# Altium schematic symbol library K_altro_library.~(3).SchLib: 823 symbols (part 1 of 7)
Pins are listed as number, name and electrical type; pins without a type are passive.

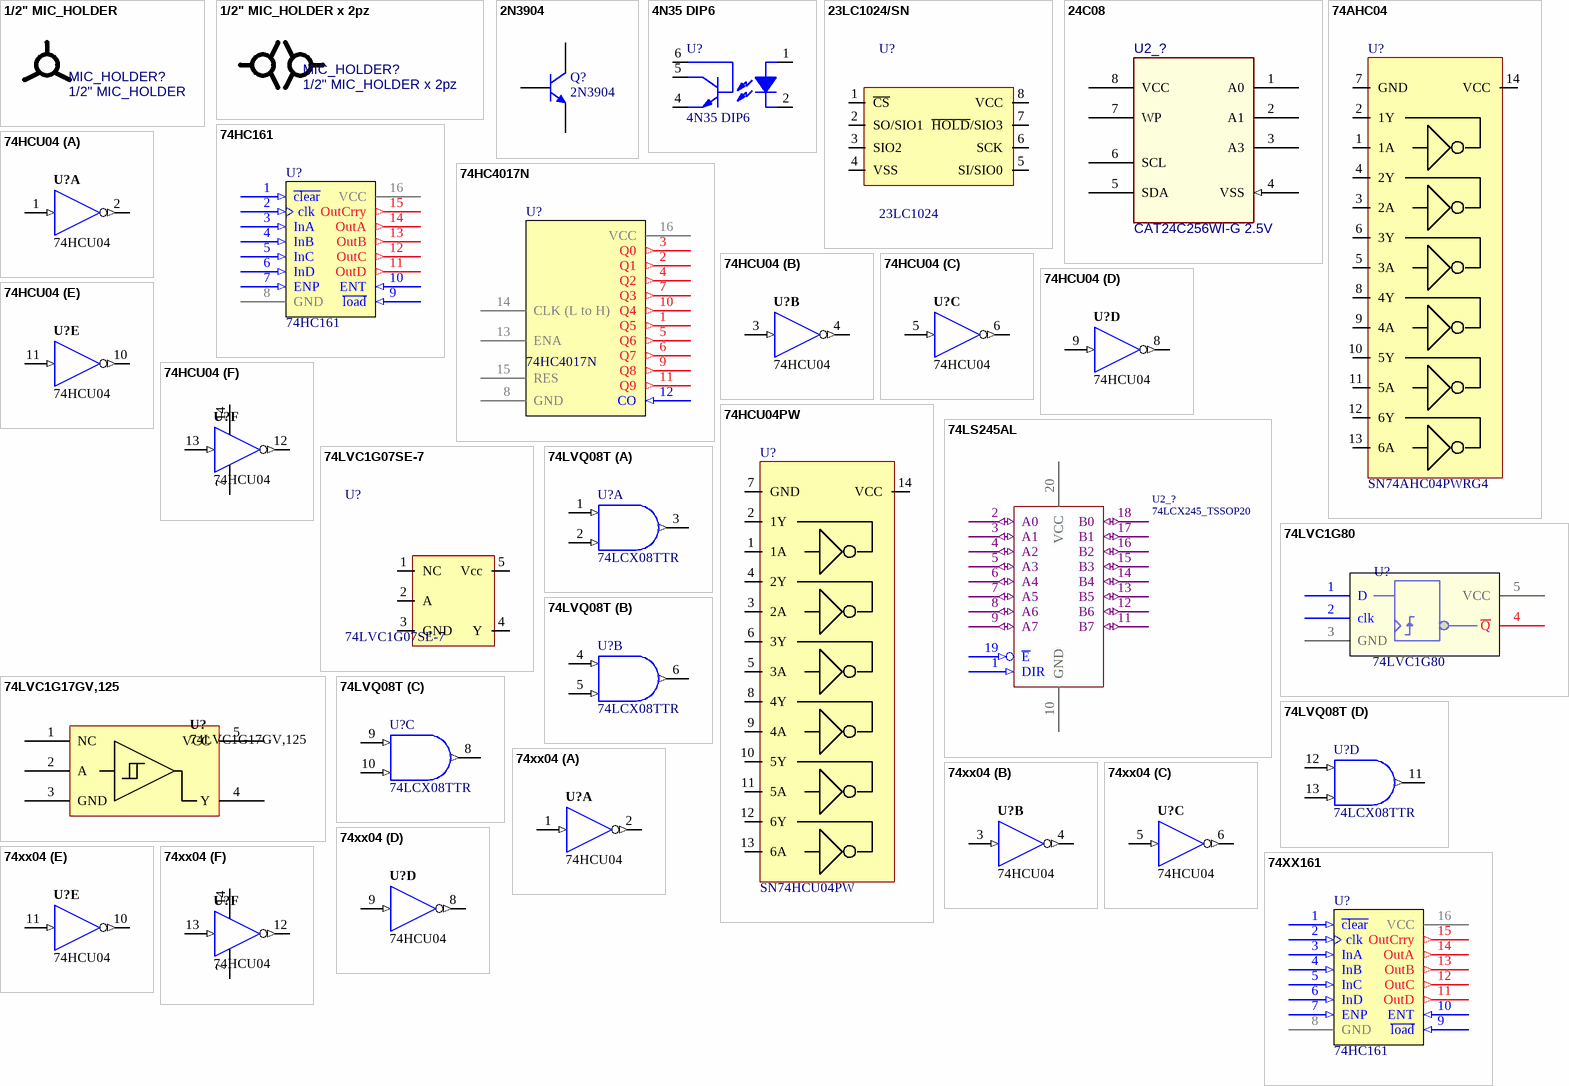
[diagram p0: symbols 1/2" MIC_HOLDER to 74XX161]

## 1/2" MIC_HOLDER
designator MIC_HOLDER?
Costo: 0,025; Aggiornato: S; ContoLavoro: 1
footprint MICROPHONE TSB-160AUC680-GP

## 1/2" MIC_HOLDER x 2pz
designator MIC_HOLDER?  (no BOM)
Costo: 0; Aggiornato: S; ContoLavoro: 1
footprint MICROPHONE_TSB-160AUC680-GP_Doppio_supporto

## 2N3904
designator Q?
NPN General Purpose Amplifier; Aggiornato: NO; Costo: 0
footprint TO-92A (TO, Flat Index; 3 In-Line, Axial Leads; Body Dia. 4.5mm; Leads 0.51 x 0.48 mm (max))
simulation model 2N3904 (NPN)
signal-integrity model 2N3904
pins: 1 E, 2 B, 3 C

## 4N35 DIP6
designator U?
Costo: 0; Aggiornato: NO
footprint DIP6
pins: 1, 2, 4, 5, 6

## 23LC1024/SN
designator U?, comment 23LC1024
23LC1024 1 Mbit SPI Bus Serial RAM 8 pin SOIC; MPN: 25AA1024; Costo: 0,39; Detail: € RS pz>40; Aggiornato: S; ContoLavoro: 0
footprint SOIC8
pins: 1 ~{CS}, 2 SO/SIO1, 3 SIO2, 4 VSS, 5 SI/SIO0, 6 SCK, 7 ~{HOLD}/SIO3, 8 VCC

## 24C08
designator U2_?, comment CAT24C256WI-G 2.5V
Aggiornato: NO; Costo: 0
footprint SO8
pins: 1 A0, 2 A1, 3 A3, 4 VSS (in), 5 SDA, 6 SCL, 7 WP, 8 VCC

## 74AHC04
designator U?, comment SN74AHC04PWRG4
Costo: 0,073; Aggiornato: NO; ContoLavoro: 0
footprint TSSOP14
pins: 1 1A, 2 1Y, 3 2A, 4 2Y, 5 3A, 6 3Y, 7 GND, 8 4Y, 9 4A, 10 5Y, 11 5A, 12 6Y, 13 6A, 14 VCC

## 74HC161
designator U?
74HC161 4 Bit Sync counter; Costo: 0,10; Aggiornato: s; ContoLavoro: 0
footprint tssop16
pins: 1 ~{clear} (in), 2 clk (in), 3 InA (in), 4 InB (in), 5 InC (in), 6 InD (in), 7 ENP (in), 8 GND (power), 9 ~{load} (in), 10 ENT (in), 11 OutD (out), 12 OutC (out), 13 OutB (out), 14 OutA (out), 15 OutCrry (out), 16 VCC (power)

## 74HC4017N
designator U?
Costo: 0,958; Aggiornato: s; ContoLavoro: 0
footprint DIP.100/16/W.300/L.775
pins: 1 Q5 (out), 2 Q1 (out), 3 Q0 (out), 4 Q2 (out), 5 Q6 (out), 6 Q7 (out), 7 Q3 (out), 8 GND (power), 9 Q8 (out), 10 Q4 (out), 11 Q9 (out), 12 CO (in), 13 ENA (power), 14 CLK (L to H) (power), 15 RES (power), 16 VCC (power)

## 74HCU04
designator U?
74HCU04, HEX Inverter, Unbuffered; Aggiornato: NO; Costo: 0,134; ContoLavoro: 0
footprint so14
part A pins: 1 A (in), 2 Y (out)
part B pins: 3 A (in), 4 Y (out)
part C pins: 5 A (in), 6 Y (out)
part D pins: 8 Y (out), 9 A (in)
part E pins: 10 Y (out), 11 A (in)
part F pins: 7 GND (power), 12 Y (out), 13 A (in), 14 VCC (power)

## 74HCU04PW
designator U?, comment SN74HCU04PW
74HCU04PW; Costo: 0,09; Detail: Prezzo RS>100pz; Aggiornato: s; ContoLavoro: 0
footprint TSSOP14
pins: 1 1A, 2 1Y, 3 2A, 4 2Y, 5 3A, 6 3Y, 7 GND, 8 4Y, 9 4A, 10 5Y, 11 5A, 12 6Y, 13 6A, 14 VCC

## 74LS245AL
designator U2_?, comment 74LCX245_TSSOP20
MPN: TC74LCX245FTCT-ND; Detail: DK TC74LCX245FTCT-ND; Aggiornato: NO; Costo: 0
footprint DIP20
footprint SO-20
footprint TSSOP20
footprint TSOP65P640-20AN (TSOP, 20-Leads, Body 6.5x4.4mm, Pitch 0.65mm, IPC Medium Density)
pins: 1 DIR (in), 2 A0 (io), 3 A1 (io), 4 A2 (io), 5 A3 (io), 6 A4 (io), 7 A5 (io), 8 A6 (io), 9 A7 (io), 10 GND (power), 11 B7 (io), 12 B6 (io), 13 B5 (io), 14 B4 (io), 15 B3 (io), 16 B2 (io), 17 B1 (io), 18 B0 (io), 19 ~{E} (in), 20 VCC (power)
2 alternate drawings of the same symbol

## 74LVC1G07SE-7
designator U?
74LVC1G07SE-7 BUFFER/DRIVER; Costo: 0,06; Aggiornato: s; ContoLavoro: 0
footprint SOT-353 (Footprint not found)
pins: 1 NC, 2 A, 3 GND, 4 Y, 5 Vcc

## 74LVC1G17GV,125
designator U?
74LVC1G17 provides a buffer function with Schmitt trigger input; Aggiornato: SI; Costo: 0,08; Detail: (RS per >1000pz)  Mouser; ContoLavoro: 0
footprint SOT95P275X110-5N
pins: 1 NC "The NCP630 is active when a voltage greater than 2.0V is applied. The NCP630 will be placed into a shutdown mode when a voltage less than 0.8V is applied. If unused then connect the pin high.", 2 A, 3 GND, 4 Y, 5 VCC "Maintans 1.216V between itself and GND"

## 74LVC1G80
designator U?
74LVC1G80 Flip Flop D; MPN: SN74LVC1G80DCKR; Costo: 0,246; Aggiornato: NO; ContoLavoro: 0
footprint DCK-5
pins: 1 D, 2 clk, 3 GND (power), 4 ~{Q}, 5 VCC (power)

## 74LVQ08T
designator U?, comment 74LCX08TTR
Quad 2-Input AND Gate; Aggiornato: NO; Costo: 0
footprint TSSOP14 (Shrink Small Outline; 14 Leads; Body Width 4.4 mm; Pitch 0.65 mm)
3D model TSSOP14 (Shrink Small Outline; 14 Leads; Body Width 4.4 mm; Pitch 0.65 mm)
pins on every part: 7 GND_POWER (power) hidden to GND_POWER, 14 D2V8 (power) hidden to D2V8
part A pins: 1 A (in), 2 B (in), 3 Y (out)
part B pins: 4 A (in), 5 B (in), 6 Y (out)
part C pins: 8 Y (out), 9 A (in), 10 B (in)
part D pins: 11 Y (out), 12 A (in), 13 B (in)

## 74xx04
designator U?, comment 74HCU04
74HCU04, HEX Inverter, Unbuffered; Aggiornato: NO; Costo: 0
footprint SOIC127P600-14
footprint TSSOP14
part A pins: 1 A (in), 2 Y (out)
part B pins: 3 A (in), 4 Y (out)
part C pins: 5 A (in), 6 Y (out)
part D pins: 8 Y (out), 9 A (in)
part E pins: 10 Y (out), 11 A (in)
part F pins: 7 GND (power), 12 Y (out), 13 A (in), 14 VCC (power)

## 74XX161
designator U?, comment 74HC161
4 Bit Sync counter; Part Field 1: ST M74HC161TTR; Costo: 0; Aggiornato: NO
footprint TSOP640-16AN (TSOP, 16-Leads, Body 5x4.4mm, Pitch 0.65mm, IPC Medium Density)
pins: 1 ~{clear} (in), 2 clk (in), 3 InA (in), 4 InB (in), 5 InC (in), 6 InD (in), 7 ENP (in), 8 GND (power), 9 ~{load} (in), 10 ENT (in), 11 OutD (out), 12 OutC (out), 13 OutB (out), 14 OutA (out), 15 OutCrry (out), 16 VCC (power)

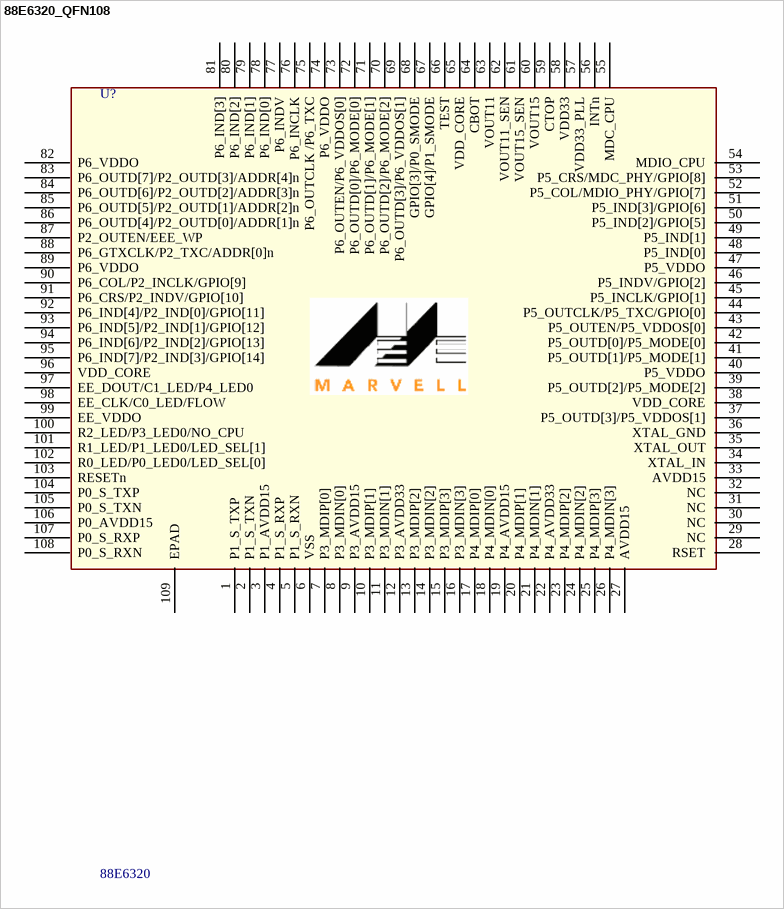
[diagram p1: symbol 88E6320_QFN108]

## 88E6320_QFN108
designator U?, comment 88E6320
Gigabit SWITCH QFN108  88E6320; Costo: 8,00; HPcode: IC88E6320; ContoLavoro: 1
footprint 88E6320_QFN108_12mmX12mm (Footprint not found)
pins: 1 P1_S_TXP, 2 P1_S_TXN, 3 P1_AVDD15, 4 P1_S_RXP, 5 P1_S_RXN, 6 VSS, 7 P3_MDIP[0], 8 P3_MDIN[0], 9 P3_AVDD15, 10 P3_MDIP[1], 11 P3_MDIN[1], 12 P3_AVDD33, 13 P3_MDIP[2], 14 P3_MDIN[2], 15 P3_MDIP[3], 16 P3_MDIN[3], 17 P4_MDIP[0], 18 P4_MDIN[0], 19 P4_AVDD15, 20 P4_MDIP[1], 21 P4_MDIN[1], 22 P4_AVDD33, 23 P4_MDIP[2], 24 P4_MDIN[2], 25 P4_MDIP[3], 26 P4_MDIN[3], 27 AVDD15, 28 RSET, 29 NC, 30 NC, 31 NC, 32 NC, 33 AVDD15, 34 XTAL_IN, 35 XTAL_OUT, 36 XTAL_GND, 37 P5_OUTD[3]/P5_VDDOS[1], 38 VDD_CORE, 39 P5_OUTD[2]/P5_MODE[2], 40 P5_VDDO, 41 P5_OUTD[1]/P5_MODE[1], 42 P5_OUTD[0]/P5_MODE[0], 43 P5_OUTEN/P5_VDDOS[0], 44 P5_OUTCLK/P5_TXC/GPIO[0], 45 P5_INCLK/GPIO[1], 46 P5_INDV/GPIO[2], 47 P5_VDDO, 48 P5_IND[0], 49 P5_IND[1], 50 P5_IND[2]/GPIO[5], 51 P5_IND[3]/GPIO[6], 52 P5_COL/MDIO_PHY/GPIO[7], 53 P5_CRS/MDC_PHY/GPIO[8], 54 MDIO_CPU, 55 MDC_CPU, 56 INTn, 57 VDD33_PLL, 58 VDD33, 59 CTOP, 60 VOUT15, 61 VOUT15_SEN, 62 VOUT11_SEN, 63 VOUT11, 64 CBOT, 65 VDD_CORE, 66 TEST, 67 GPIO[4]/P1_SMODE, 68 GPIO[3]/P0_SMODE, 69 P6_OUTD[3]/P6_VDDOS[1], 70 P6_OUTD[2]/P6_MODE[2], 71 P6_OUTD[1]/P6_MODE[1], 72 P6_OUTD[0]/P6_MODE[0], 73 P6_OUTEN/P6_VDDOS[0], 74 P6_VDDO, 75 P6_OUTCLK /P6_TXC, 76 P6_INCLK, 77 P6_INDV, 78 P6_IND[0], 79 P6_IND[1], 80 P6_IND[2], 81 P6_IND[3], 82 P6_VDDO, 83 P6_OUTD[7]/P2_OUTD[3]/ADDR[4]n, 84 P6_OUTD[6]/P2_OUTD[2]/ADDR[3]n, 85 P6_OUTD[5]/P2_OUTD[1]/ADDR[2]n, 86 P6_OUTD[4]/P2_OUTD[0]/ADDR[1]n, 87 P2_OUTEN/EEE_WP, 88 P6_GTXCLK/P2_TXC/ADDR[0]n, 89 P6_VDDO, 90 P6_COL/P2_INCLK/GPIO[9], 91 P6_CRS/P2_INDV/GPIO[10], 92 P6_IND[4]/P2_IND[0]/GPIO[11], 93 P6_IND[5]/P2_IND[1]/GPIO[12], 94 P6_IND[6]/P2_IND[2]/GPIO[13], 95 P6_IND[7]/P2_IND[3]/GPIO[14], 96 VDD_CORE, 97 EE_DOUT/C1_LED/P4_LED0, 98 EE_CLK/C0_LED/FLOW, 99 EE_VDDO, 100 R2_LED/P3_LED0/NO_CPU, 101 R1_LED/P1_LED0/LED_SEL[1], 102 R0_LED/P0_LED0/LED_SEL[0], 103 RESETn, 104 P0_S_TXP, 105 P0_S_TXN, 106 P0_AVDD15, 107 P0_S_RXP, 108 P0_S_RXN, 109 EPAD

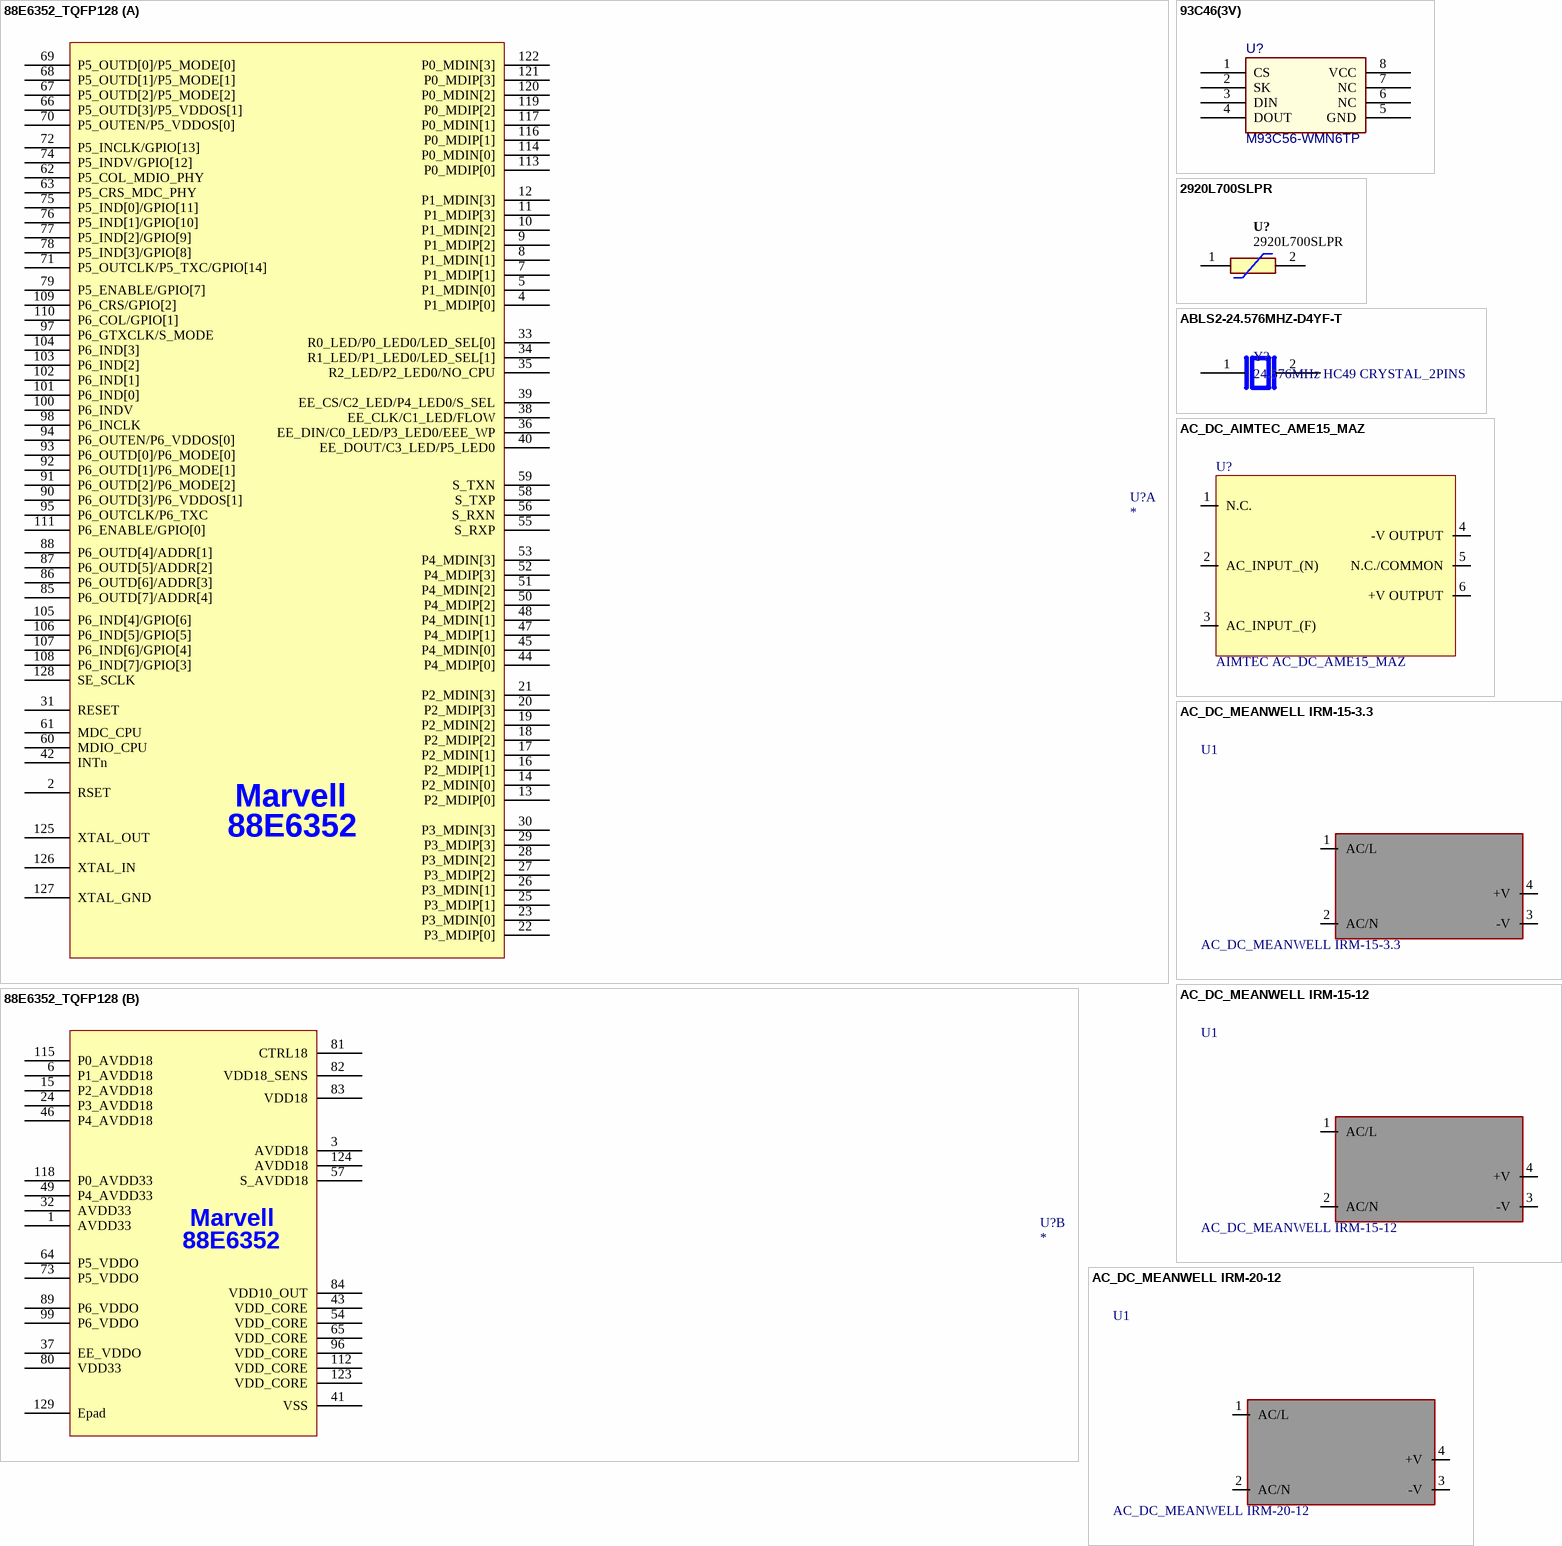
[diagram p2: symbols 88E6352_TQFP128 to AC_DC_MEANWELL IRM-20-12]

## 88E6352_TQFP128
designator U?
MPN: 88E6352; Aggiornato: NO; Costo: 20,0; ContoLavoro: 1
footprint TQFP128
part A pins: 2 RSET, 4 P1_MDIP[0], 5 P1_MDIN[0], 7 P1_MDIP[1], 8 P1_MDIN[1], 9 P1_MDIP[2], 10 P1_MDIN[2], 11 P1_MDIP[3], 12 P1_MDIN[3], 13 P2_MDIP[0], 14 P2_MDIN[0], 16 P2_MDIP[1], 17 P2_MDIN[1], 18 P2_MDIP[2], 19 P2_MDIN[2], 20 P2_MDIP[3], 21 P2_MDIN[3], 22 P3_MDIP[0], 23 P3_MDIN[0], 25 P3_MDIP[1], 26 P3_MDIN[1], 27 P3_MDIP[2], 28 P3_MDIN[2], 29 P3_MDIP[3], 30 P3_MDIN[3], 31 RESET, 33 R0_LED/P0_LED0/LED_SEL[0], 34 R1_LED/P1_LED0/LED_SEL[1], 35 R2_LED/P2_LED0/NO_CPU, 36 EE_DIN/C0_LED/P3_LED0/EEE_WP, 38 EE_CLK/C1_LED/FLOW, 39 EE_CS/C2_LED/P4_LED0/S_SEL, 40 EE_DOUT/C3_LED/P5_LED0, 42 INTn, 44 P4_MDIP[0], 45 P4_MDIN[0], 47 P4_MDIP[1], 48 P4_MDIN[1], 50 P4_MDIP[2], 51 P4_MDIN[2], 52 P4_MDIP[3], 53 P4_MDIN[3], 55 S_RXP, 56 S_RXN, 58 S_TXP, 59 S_TXN, 60 MDIO_CPU, 61 MDC_CPU, 62 P5_COL_MDIO_PHY, 63 P5_CRS_MDC_PHY, 66 P5_OUTD[3]/P5_VDDOS[1], 67 P5_OUTD[2]/P5_MODE[2], 68 P5_OUTD[1]/P5_MODE[1], 69 P5_OUTD[0]/P5_MODE[0], 70 P5_OUTEN/P5_VDDOS[0], 71 P5_OUTCLK/P5_TXC/GPIO[14], 72 P5_INCLK/GPIO[13], 74 P5_INDV/GPIO[12], 75 P5_IND[0]/GPIO[11], 76 P5_IND[1]/GPIO[10], 77 P5_IND[2]/GPIO[9], 78 P5_IND[3]/GPIO[8], 79 P5_ENABLE/GPIO[7], 85 P6_OUTD[7]/ADDR[4], 86 P6_OUTD[6]/ADDR[3], 87 P6_OUTD[5]/ADDR[2], 88 P6_OUTD[4]/ADDR[1], 90 P6_OUTD[3]/P6_VDDOS[1], 91 P6_OUTD[2]/P6_MODE[2], 92 P6_OUTD[1]/P6_MODE[1], 93 P6_OUTD[0]/P6_MODE[0], 94 P6_OUTEN/P6_VDDOS[0], 95 P6_OUTCLK/P6_TXC, 97 P6_GTXCLK/S_MODE, 98 P6_INCLK, 100 P6_INDV, 101 P6_IND[0], 102 P6_IND[1], 103 P6_IND[2], 104 P6_IND[3], 105 P6_IND[4]/GPIO[6], 106 P6_IND[5]/GPIO[5], 107 P6_IND[6]/GPIO[4], 108 P6_IND[7]/GPIO[3], 109 P6_CRS/GPIO[2], 110 P6_COL/GPIO[1], 111 P6_ENABLE/GPIO[0], 113 P0_MDIP[0], 114 P0_MDIN[0], 116 P0_MDIP[1], 117 P0_MDIN[1], 119 P0_MDIP[2], 120 P0_MDIN[2], 121 P0_MDIP[3], 122 P0_MDIN[3], 125 XTAL_OUT, 126 XTAL_IN, 127 XTAL_GND (power), 128 SE_SCLK
part B pins: 1 AVDD33 (power), 3 AVDD18 (power), 6 P1_AVDD18 (power), 15 P2_AVDD18 (power), 24 P3_AVDD18 (power), 32 AVDD33 (power), 37 EE_VDDO (power), 41 VSS (power), 43 VDD_CORE (power), 46 P4_AVDD18 (power), 49 P4_AVDD33 (power), 54 VDD_CORE (power), 57 S_AVDD18 (power), 64 P5_VDDO (power), 65 VDD_CORE (power), 73 P5_VDDO (power), 80 VDD33 (power), 81 CTRL18, 82 VDD18_SENS, 83 VDD18 (power), 84 VDD10_OUT (power), 89 P6_VDDO (power), 96 VDD_CORE (power), 99 P6_VDDO (power), 112 VDD_CORE (power), 115 P0_AVDD18 (power), 118 P0_AVDD33 (power), 123 VDD_CORE (power), 124 AVDD18 (power), 129 Epad (power)

## 93C46(3V)
designator U?, comment M93C56-WMN6TP
MPN: M93C56; Costo: 0,0334; Aggiornato: NO; ContoLavoro: 0
footprint SO8
footprint SOIC150-8N (SOIC, 8-Leads, Body 4.9x3.9mm, Pitch 1.27mm, IPC Medium Density)
pins: 1 CS, 2 SK, 3 DIN, 4 DOUT, 5 GND, 6 NC, 7 NC, 8 VCC

## 2920L700SLPR
designator U?
Fusibile ripristinabile Wickmann, intervento a 14A in 0.2s, 6V cc, tenuta 7A, 7mΩ max; Aggiornato: SI; Costo: 2,78; Detail: € 2,778 PZ 5 - 245 (RS) Codice RS: 174-0763; ContoLavoro: 0
footprint 2920L700SLPR
pins: 1, 2

## ABLS2-24.576MHZ-D4YF-T
designator Y?, comment 24.576MHz HC49 CRYSTAL_2PINS
Crystal 24.576MHz ±30ppm (Tol) ±30ppm (Stability) 18pF FUND 40Ohm 2-Pin HC-49/US SMD T/R; Detail: prezzo Mouser 10pz; Costo: 0,336; ContoLavoro: 0
footprint XTAL_ABLS2-24.576MHZ-D4YF-T
pins: 1, 1, 2, 2

## AC_DC_AIMTEC_AME15_MAZ
designator U?, comment AIMTEC AC_DC_AME15_MAZ
MPN: AME15-3.3SMAZ; Costo: 20; Aggiornato: NO; ContoLavoro: 0
footprint AC_DC AIMTEC AME15_MAZ
pins: 1 N.C., 2 AC_INPUT_(N), 3 AC_INPUT_(F), 4 -V OUTPUT, 5 N.C./COMMON, 6 +V OUTPUT

## AC_DC_MEANWELL IRM-15-3.3
designator U1
Costo: 13; Aggiornato: NO; ContoLavoro: 0
footprint AC_DC MEANWELL_IRM-15_IRM-20 (AC_DC MEANWELL IRM-15 IRM-20)
pins: 1 AC/L, 2 AC/N, 3 -V, 4 +V

## AC_DC_MEANWELL IRM-15-12
designator U1
meanwell 12v 1.25A IRM-15-12; Costo: 7; Aggiornato: NO; ContoLavoro: 0
footprint AC_DC MEANWELL_IRM-15_IRM-20 (AC_DC MEANWELL IRM-15 IRM-20)
pins: 1 AC/L, 2 AC/N, 3 -V, 4 +V

## AC_DC_MEANWELL IRM-20-12
designator U1
meanwell 12v 1.8A IRM-20-12; Costo: 8; HPcode: ALIACDC12V1.8A; Aggiornato: n; ContoLavoro: 1
footprint AC_DC MEANWELL_IRM-15_IRM-20 (AC_DC MEANWELL IRM-15 IRM-20)
pins: 1 AC/L, 2 AC/N, 3 -V, 4 +V

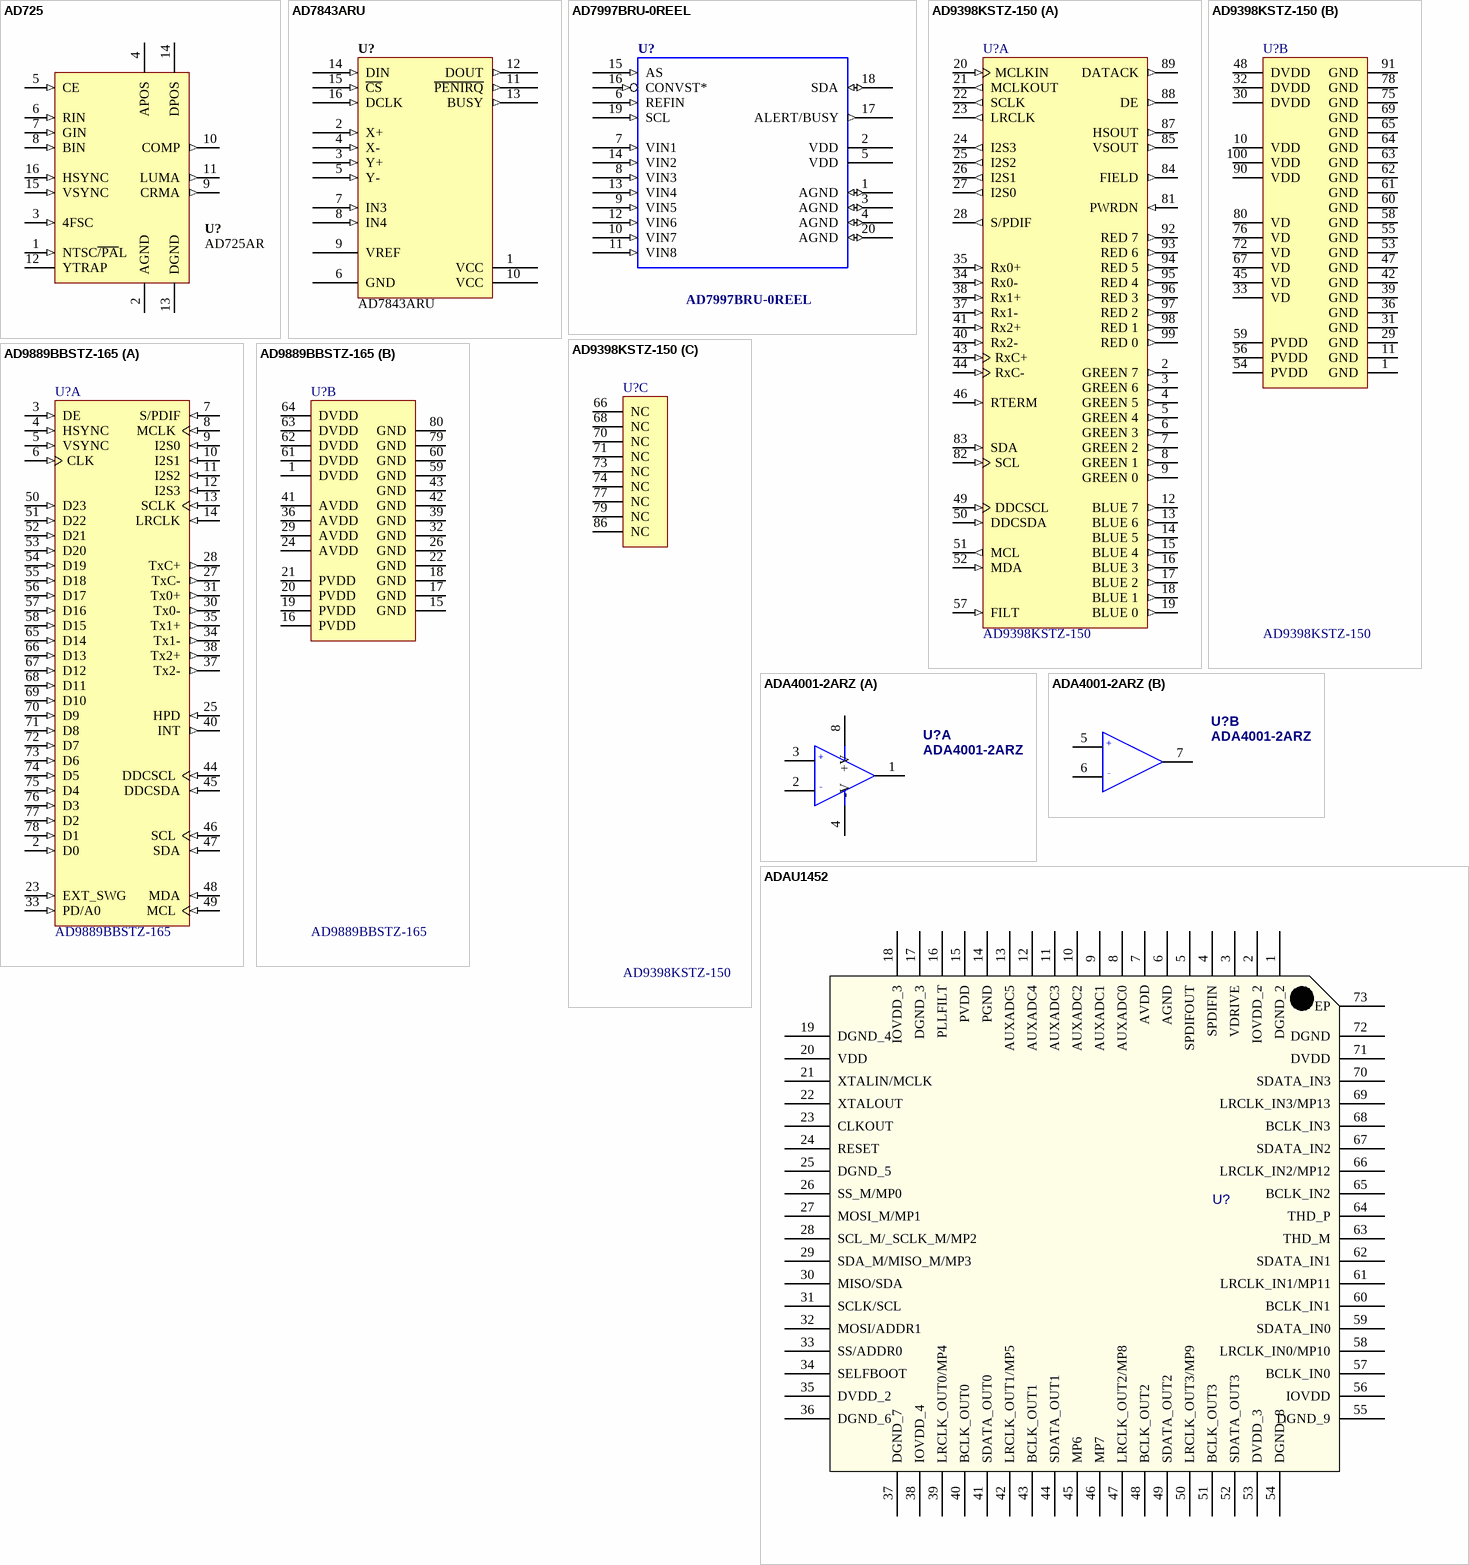
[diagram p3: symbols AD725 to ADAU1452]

## AD725
designator U?, comment AD725AR
AD725AR, Low Cost RGB to NTSC/PAL Encoder with Luma Trap Port; Aggiornato: NO; Costo: 0
footprint SOP127P1033-16 (Footprint not found)
pins: 1 NTSC~{/PA}L (in) "Encoding Standard Pin.", 2 AGND (power) "Analog Ground Connection.", 3 4FSC (in) "4FSC Clock Input.", 4 APOS (power) "Analog Positive Supply", 5 CE (in) "Chip Enable.", 6 RIN (in) "Red Component Video Input.", 7 GIN (in) "Green Component Video Input.", 8 BIN (in) "Blue Component Video Input.", 9 CRMA (out) "Chrominance Output.*", 10 COMP (out) "Composite Video Output.*", 11 LUMA (out) "Luminance plus CSYNC Output.*", 12 YTRAP "Luminance Trap Filter Tap.", 13 DGND (power) "Digital Ground Connection.", 14 DPOS (power) "Digital Positive Supply", 15 VSYNC (in) "Vertical Sync Signal", 16 HSYNC (in) "Horizontal Sync Signal"

## AD7843ARU
designator U?
AD7843ARU,12-bit SPI Touch Screen Digitizer; Supply Voltage: mV; Aggiornato: NO; Costo: 0
footprint TSOP65P638-16
pins: 1 VCC (power), 2 X+ (in), 3 Y+ (in), 4 X- (in), 5 Y- (in), 6 GND (power), 7 IN3 (in), 8 IN4 (in), 9 VREF, 10 VCC (power), 11 ~{PENIRQ} (out), 12 DOUT (out), 13 BUSY (out), 14 DIN (in), 15 ~{CS} (in), 16 DCLK (in)

## AD7997BRU-0REEL
designator U?
Aggiornato: NO; Costo: 0
footprint SSOP_20
pins: 1 AGND (io), 2 VDD (power), 3 AGND (io), 4 AGND (io), 5 VDD (power), 6 REFIN (in), 7 VIN1 (in), 8 VIN3 (in), 9 VIN5 (in), 10 VIN7 (in), 11 VIN8 (in), 12 VIN6 (in), 13 VIN4 (in), 14 VIN2 (in), 15 AS (in), 16 CONVST* (in), 17 ALERT/BUSY (out), 18 SDA (io), 19 SCL (in), 20 AGND (io)
2 alternate drawings of the same symbol

## AD9398KSTZ-150
designator U?
AD9398KSTZ-150, HDMI Video Receiver, TQFP100; Supply Voltage: mV; Aggiornato: NO; Costo: 0
footprint ST-100-1_V
part A pins: 2 GREEN 7 (out) "Output of Green Converter, Bit 7 is MSB", 3 GREEN 6 (out) "Output of Green Converter, Bit 7 is MSB", 4 GREEN 5 (out) "Output of Green Converter, Bit 7 is MSB", 5 GREEN 4 (out) "Output of Green Converter, Bit 7 is MSB", 6 GREEN 3 (out) "Output of Green Converter, Bit 7 is MSB", 7 GREEN 2 (out) "Output of Green Converter, Bit 7 is MSB", 8 GREEN 1 (out) "Output of Green Converter, Bit 7 is MSB", 9 GREEN 0 (out) "Output of Green Converter, Bit 7 is MSB", 12 BLUE 7 (out) "Output of Blue Converter, Bit 7 is MSB", 13 BLUE 6 (out) "Output of Blue Converter, Bit 7 is MSB", 14 BLUE 5 (out) "Output of Blue Converter, Bit 7 is MSB", 15 BLUE 4 (out) "Output of Blue Converter, Bit 7 is MSB", 16 BLUE 3 (out) "Output of Blue Converter, Bit 7 is MSB", 17 BLUE 2 (out) "Output of Blue Converter, Bit 7 is MSB", 18 BLUE 1 (out) "Output of Blue Converter, Bit 7 is MSB", 19 BLUE 0 (out) "Output of Blue Converter, Bit 7 is MSB", 20 MCLKIN (in) "External Reference Audio Clock In", 21 MCLKOUT (out) "Audio Master Clock Output", 22 SCLK (out) "Audio Serial Clock Output", 23 LRCLK (out) "Data Output Clock for Left and Right Audio Channels", 24 I2S3 (out) "I2S Audio (Channel 7, Channel 8)", 25 I2S2 (out) "I2S Audio (Channel 5, Channel 6)", 26 I2S1 (out) "I2S Audio (Channel 3, Channel 4)", 27 I2S0 (out) "I2S Audio (Channel 1, Channel 2)", 28 S/PDIF (out) "S/PDIF Digital Audio Output", 34 Rx0- (in) "Digital Input Channel 0 Complement", 35 Rx0+ (in) "Digital Input Channel 0 True", 37 Rx1- (in) "Digital Input Channel 1 Complement", 38 Rx1+ (in) "Digital Input Channel 1 True", 40 Rx2- (in) "Digital Input Channel 2 Complement", 41 Rx2+ (in) "Digital Input Channel 2 True", 43 RxC+ (in) "Digital Data Clock True", 44 RxC- (in) "Digital Data Clock Complement", 46 RTERM (in) "Sets Internal Termination Resistance", 49 DDCSCL (in) "HDCP Slave Serial Port Data Clock", 50 DDCSDA (in) "HDCP Slave Serial Port Data I/O", 51 MCL (out) "HDCP Master Serial Port Data Clock", 52 MDA (in) "HDCP Master Serial Port Data I/O", 57 FILT (in) "Connection for External Filter Components for audio PLL", 81 PWRDN (in) "Power-Down Control", 82 SCL (in) "Serial Port Data Clock", 83 SDA (in) "Serial Port Data I/O", 84 FIELD (out) "Odd/Even Field Output", 85 VSOUT (out) "VSYNC Output Clock (Phase-Aligned with DATACK)", 87 HSOUT (out) "HSYNC Output Clock (Phase-Aligned with DATACK)", 88 DE (out) "Data Enable", 89 DATACK (out) "Data Output Clock", 92 RED 7 (out) "Output of Red Converter, Bit 7 is MSB", 93 RED 6 (out) "Output of Red Converter, Bit 7 is MSB", 94 RED 5 (out) "Output of Red Converter, Bit 7 is MSB", 95 RED 4 (out) "Output of Red Converter, Bit 7 is MSB", 96 RED 3 (out) "Output of Red Converter, Bit 7 is MSB", 97 RED 2 (out) "Output of Red Converter, Bit 7 is MSB", 98 RED 1 (out) "Output of Red Converter, Bit 7 is MSB", 99 RED 0 (out) "Output of Red Converter, Bit 7 is MSB"
part B pins: 1 GND (power) "Ground", 10 VDD (power) "Output Power Supply", 11 GND (power) "Ground", 29 GND (power) "Ground", 30 DVDD (power) "Digital Logic Power Supply", 31 GND (power) "Ground", 32 DVDD (power) "Digital Logic Power Supply", 33 VD (power) "Analog Power Supply and DVI Terminators", 36 GND (power) "Ground", 39 GND (power) "Ground", 42 GND (power) "Ground", 45 VD (power) "Analog Power Supply and DVI Terminators", 47 GND (power) "Ground", 48 DVDD (power) "Digital Logic Power Supply", 53 GND (power) "Ground", 54 PVDD (power) "PLL Power Supply", 55 GND (power) "Ground", 56 PVDD (power) "PLL Power Supply", 58 GND (power) "Ground", 59 PVDD (power) "PLL Power Supply", 60 GND (power) "Ground", 61 GND (power) "Ground", 62 GND (power) "Ground", 63 GND (power) "Ground", 64 GND (power) "Ground", 65 GND (power) "Ground", 67 VD (power) "Analog Power Supply and DVI Terminators", 69 GND (power) "Ground", 72 VD (power) "Analog Power Supply and DVI Terminators", 75 GND (power) "Ground", 76 VD (power) "Analog Power Supply and DVI Terminators", 78 GND (power) "Ground", 80 VD (power) "Analog Power Supply and DVI Terminators", 90 VDD (power) "Output Power Supply", 91 GND (power) "Ground", 100 VDD (power) "Output Power Supply"
part C pins: 66 NC "No Connection", 68 NC "No Connection", 70 NC "No Connection", 71 NC "No Connection", 73 NC "No Connection", 74 NC "No Connection", 77 NC "No Connection", 79 NC "No Connection", 86 NC "No Connection"

## AD9889BBSTZ-165
designator U?
AD9889, HDMI Video Transmitter, TQFP; Supply Voltage: mV; Aggiornato: NO; Costo: 0
footprint ST-80-2_V
part A pins: 2 D0 (in) "Video Data Input. Digital input in RGB or YCbCr format. Supports CMOS logic levels fro1.8 V to 3.3 V.", 3 DE (in) "Data Enable Bit for Digital Video. Supports CMOS logic levels from 1.8 V to 3.3 V.", 4 HSYNC (in) "Horizontal Sync Input. Supports CMOS logic levels from 1.8 V to 3.3 V.", 5 VSYNC (in) "Vertical Sync Input. Supports CMOS logic levels from 1.8 V to 3.3 V.", 6 CLK (in) "Video Clock Input. Supports CMOS logic levels from 1.8 V to 3.3 V.", 7 S/PDIF (in) "S/PDIF (Sony/Philips Digital Interface) Audio Input.", 8 MCLK (in) "Audio Reference Clock. 128 x N x fSwith N = 1, 2, 3, or 4.", 9 I2S0 (in) "I2S Audio Data Input. These represent the eight channels of audio (two per input) available through I2S.", 10 I2S1 (in) "I2S Audio Data Input. These represent the eight channels of audio (two per input) available through I2S.", 11 I2S2 (in) "I2S Audio Data Input. These represent the eight channels of audio (two per input) available through I2S.", 12 I2S3 (in) "I2S Audio Data Input. These represent the eight channels of audio (two per input) available through I2S.", 13 SCLK (in) "I2S Audio Clock. Supports CMOS logic levels from 1.8 V to 3.3 V.", 14 LRCLK (in) "Left/Right Channel Selection. Supports CMOS logic levels from 1.8 V to 3.3 V.", 23 EXT_SWG (in) "Set Internal Reference Currents. Place 887Ohm resistor (1% tolerance) between this pand ground.", 25 HPD (in) "Hot Plug Detect Signal. This indicates to the interface whether the receiver is connected. 1.8 V to 5.0 V CMOS logic levels.", 27 TxC- (out) "Differential Clock Output. Differential clock output at pixel clock rate; TMDS logic level.", 28 TxC+ (out) "Differential Clock Output. Differential clock output at pixel clock rate; TMDS logic level.", 30 Tx0- (out) "Differential Output Channel 0. Differential output of the blue data at 10x the pixel clock rate; TMDS logic level.", 31 Tx0+ (out) "Differential Output Channel 0. Differential output of the blue data at 10x the pixel clock rate; TMDS logic level.", 33 PD/A0 (in) "Power-Down Control and I2C Address Selection.", 34 Tx1- (out) "Differential Output Channel 1. Differential output of the green data at 10x the pixeclock rate; TMDS logic level.", 35 Tx1+ (out) "Differential Output Channel 1. Differential output of the green data at 10x the pixeclock rate; TMDS logic level.", 37 Tx2- (out) "Differential Output Channel 2. Differential output of the red data at 10x the pixel clock rate; TMDS logic level.", 38 Tx2+ (out) "Differential Output Channel 2. Differential output of the red data at 10x the pixel clock rate; TMDS logic level.", 40 INT (out) "Interrupt. Open drain. A 2 kOhm pull-up resistor to the microcontroller I/O supply is recommended. Active Low.", 44 DDCSCL (in) "Serial Port Data Clock to Receiver. This pin serves as the master clock for the DDC bus. 5 V CMOS logic level.", 45 DDCSDA (in) "Serial Port Data I/O to Receiver. This pin serves as the master to the DDC bus. 5 V CMOS logic level.", 46 SCL (in) "Serial Port Data Clock. This pin serves as the serial port data clock slave for registeraccess.", 47 SDA (in) "Serial Port Data I/O. This pin serves as the serial port data I/O slave for register access.", 48 MDA (in) "Serial Port Data I/O Master to HDCP Key EEPROM. Supports CMOS logic levels from1.8 V to 3.3 V.", 49 MCL (in) "Serial Port Data Clock Master to HDCP Key EEPROM. Supports CMOS logic levels from 1.8 V to 3.3 V.", 50 D23 (in) "Video Data Input. Digital input in RGB or YCbCr format. Supports CMOS logic levels fro1.8 V to 3.3 V.", 51 D22 (in) "Video Data Input. Digital input in RGB or YCbCr format. Supports CMOS logic levels fro1.8 V to 3.3 V.", 52 D21 (in) "Video Data Input. Digital input in RGB or YCbCr format. Supports CMOS logic levels fro1.8 V to 3.3 V.", 53 D20 (in) "Video Data Input. Digital input in RGB or YCbCr format. Supports CMOS logic levels fro1.8 V to 3.3 V.", 54 D19 (in) "Video Data Input. Digital input in RGB or YCbCr format. Supports CMOS logic levels fro1.8 V to 3.3 V.", 55 D18 (in) "Video Data Input. Digital input in RGB or YCbCr format. Supports CMOS logic levels fro1.8 V to 3.3 V.", 56 D17 (in) "Video Data Input. Digital input in RGB or YCbCr format. Supports CMOS logic levels fro1.8 V to 3.3 V.", 57 D16 (in) "Video Data Input. Digital input in RGB or YCbCr format. Supports CMOS logic levels fro1.8 V to 3.3 V.", 58 D15 (in) "Video Data Input. Digital input in RGB or YCbCr format. Supports CMOS logic levels fro1.8 V to 3.3 V.", 65 D14 (in) "Video Data Input. Digital input in RGB or YCbCr format. Supports CMOS logic levels fro1.8 V to 3.3 V.", 66 D13 (in) "Video Data Input. Digital input in RGB or YCbCr format. Supports CMOS logic levels fro1.8 V to 3.3 V.", 67 D12 (in) "Video Data Input. Digital input in RGB or YCbCr format. Supports CMOS logic levels fro1.8 V to 3.3 V.", 68 D11 (in) "Video Data Input. Digital input in RGB or YCbCr format. Supports CMOS logic levels fro1.8 V to 3.3 V.", 69 D10 (in) "Video Data Input. Digital input in RGB or YCbCr format. Supports CMOS logic levels fro1.8 V to 3.3 V.", 70 D9 (in) "Video Data Input. Digital input in RGB or YCbCr format. Supports CMOS logic levels fro1.8 V to 3.3 V.", 71 D8 (in) "Video Data Input. Digital input in RGB or YCbCr format. Supports CMOS logic levels fro1.8 V to 3.3 V.", 72 D7 (in) "Video Data Input. Digital input in RGB or YCbCr format. Supports CMOS logic levels fro1.8 V to 3.3 V.", 73 D6 (in) "Video Data Input. Digital input in RGB or YCbCr format. Supports CMOS logic levels fro1.8 V to 3.3 V.", 74 D5 (in) "Video Data Input. Digital input in RGB or YCbCr format. Supports CMOS logic levels fro1.8 V to 3.3 V.", 75 D4 (in) "Video Data Input. Digital input in RGB or YCbCr format. Supports CMOS logic levels fro1.8 V to 3.3 V.", 76 D3 (in) "Video Data Input. Digital input in RGB or YCbCr format. Supports CMOS logic levels fro1.8 V to 3.3 V.", 77 D2 (in) "Video Data Input. Digital input in RGB or YCbCr format. Supports CMOS logic levels fro1.8 V to 3.3 V.", 78 D1 (in) "Video Data Input. Digital input in RGB or YCbCr format. Supports CMOS logic levels fro1.8 V to 3.3 V."
part B pins: 1 DVDD (power) "1.8 V Power Supply for Digital and I/O Power Supply.", 15 GND (power) "Ground. The ground return for all circuitry on-chip.", 16 PVDD (power) "1.8 V PLL Power Supply.", 17 GND (power) "Ground. The ground return for all circuitry on-chip.", 18 GND (power) "Ground. The ground return for all circuitry on-chip.", 19 PVDD (power) "1.8 V PLL Power Supply.", 20 PVDD (power) "1.8 V PLL Power Supply.", 21 PVDD (power) "1.8 V PLL Power Supply.", 22 GND (power) "Ground. The ground return for all circuitry on-chip.", 24 AVDD (power) "1.8 V Power Supply for TMDS Outputs.", 26 GND (power) "Ground. The ground return for all circuitry on-chip.", 29 AVDD (power) "1.8 V Power Supply for TMDS Outputs.", 32 GND (power) "Ground. The ground return for all circuitry on-chip.", 36 AVDD (power) "1.8 V Power Supply for TMDS Outputs.", 39 GND (power) "Ground. The ground return for all circuitry on-chip.", 41 AVDD (power) "1.8 V Power Supply for TMDS Outputs.", 42 GND (power) "Ground. The ground return for all circuitry on-chip.", 43 GND (power) "Ground. The ground return for all circuitry on-chip.", 59 GND (power) "Ground. The ground return for all circuitry on-chip.", 60 GND (power) "Ground. The ground return for all circuitry on-chip.", 61 DVDD (power) "1.8 V Power Supply for Digital and I/O Power Supply.", 62 DVDD (power) "1.8 V Power Supply for Digital and I/O Power Supply.", 63 DVDD (power) "1.8 V Power Supply for Digital and I/O Power Supply.", 64 DVDD (power) "1.8 V Power Supply for Digital and I/O Power Supply.", 79 GND (power) "Ground. The ground return for all circuitry on-chip.", 80 GND (power) "Ground. The ground return for all circuitry on-chip."

## ADA4001-2ARZ
designator U?
ADA4001-2ARZ SMD DUAL OP AMP; Costo: 0,993; Aggiornato: S; ContoLavoro: 0
footprint SOIC150-8N
part A pins: 1 OUT, 2 -IN, 3 +IN, 4 -V (power), 8 +V (power)
part B pins: 5 +IN, 6 -IN, 7 OUT

## ADAU1452
designator U?
Hpcode: ICADAU1452; Aggiornato: NO; Costo: 7,45; ContoLavoro: 1
footprint LFCSP_72_EP (LFCSP 72 Exposed Pad)
footprint LFCSP_72_EP_vias (LFCSP 72 Exposed Pad VIAS)
pins: 1 DGND_2, 2 IOVDD_2, 3 VDRIVE, 4 SPDIFIN, 5 SPDIFOUT, 6 AGND, 7 AVDD, 8 AUXADC0, 9 AUXADC1, 10 AUXADC2, 11 AUXADC3, 12 AUXADC4, 13 AUXADC5, 14 PGND, 15 PVDD, 16 PLLFILT, 17 DGND_3, 18 IOVDD_3, 19 DGND_4, 20 VDD, 21 XTALIN/MCLK, 22 XTALOUT, 23 CLKOUT, 24 RESET, 25 DGND_5, 26 SS_M/MP0, 27 MOSI_M/MP1, 28 SCL_M/_SCLK_M/MP2, 29 SDA_M/MISO_M/MP3, 30 MISO/SDA, 31 SCLK/SCL, 32 MOSI/ADDR1, 33 SS/ADDR0, 34 SELFBOOT, 35 DVDD_2, 36 DGND_6, 37 DGND_7, 38 IOVDD_4, 39 LRCLK_OUT0/MP4, 40 BCLK_OUT0, 41 SDATA_OUT0, 42 LRCLK_OUT1/MP5, 43 BCLK_OUT1, 44 SDATA_OUT1, 45 MP6, 46 MP7, 47 LRCLK_OUT2/MP8, 48 BCLK_OUT2, 49 SDATA_OUT2, 50 LRCLK_OUT3/MP9, 51 BCLK_OUT3, 52 SDATA_OUT3, 53 DVDD_3, 54 DGND_8, 55 DGND_9, 56 IOVDD, 57 BCLK_IN0, 58 LRCLK_IN0/MP10, 59 SDATA_IN0, 60 BCLK_IN1, 61 LRCLK_IN1/MP11, 62 SDATA_IN1, 63 THD_M, 64 THD_P, 65 BCLK_IN2, 66 LRCLK_IN2/MP12, 67 SDATA_IN2, 68 BCLK_IN3, 69 LRCLK_IN3/MP13, 70 SDATA_IN3, 71 DVDD, 72 DGND, 73 EP

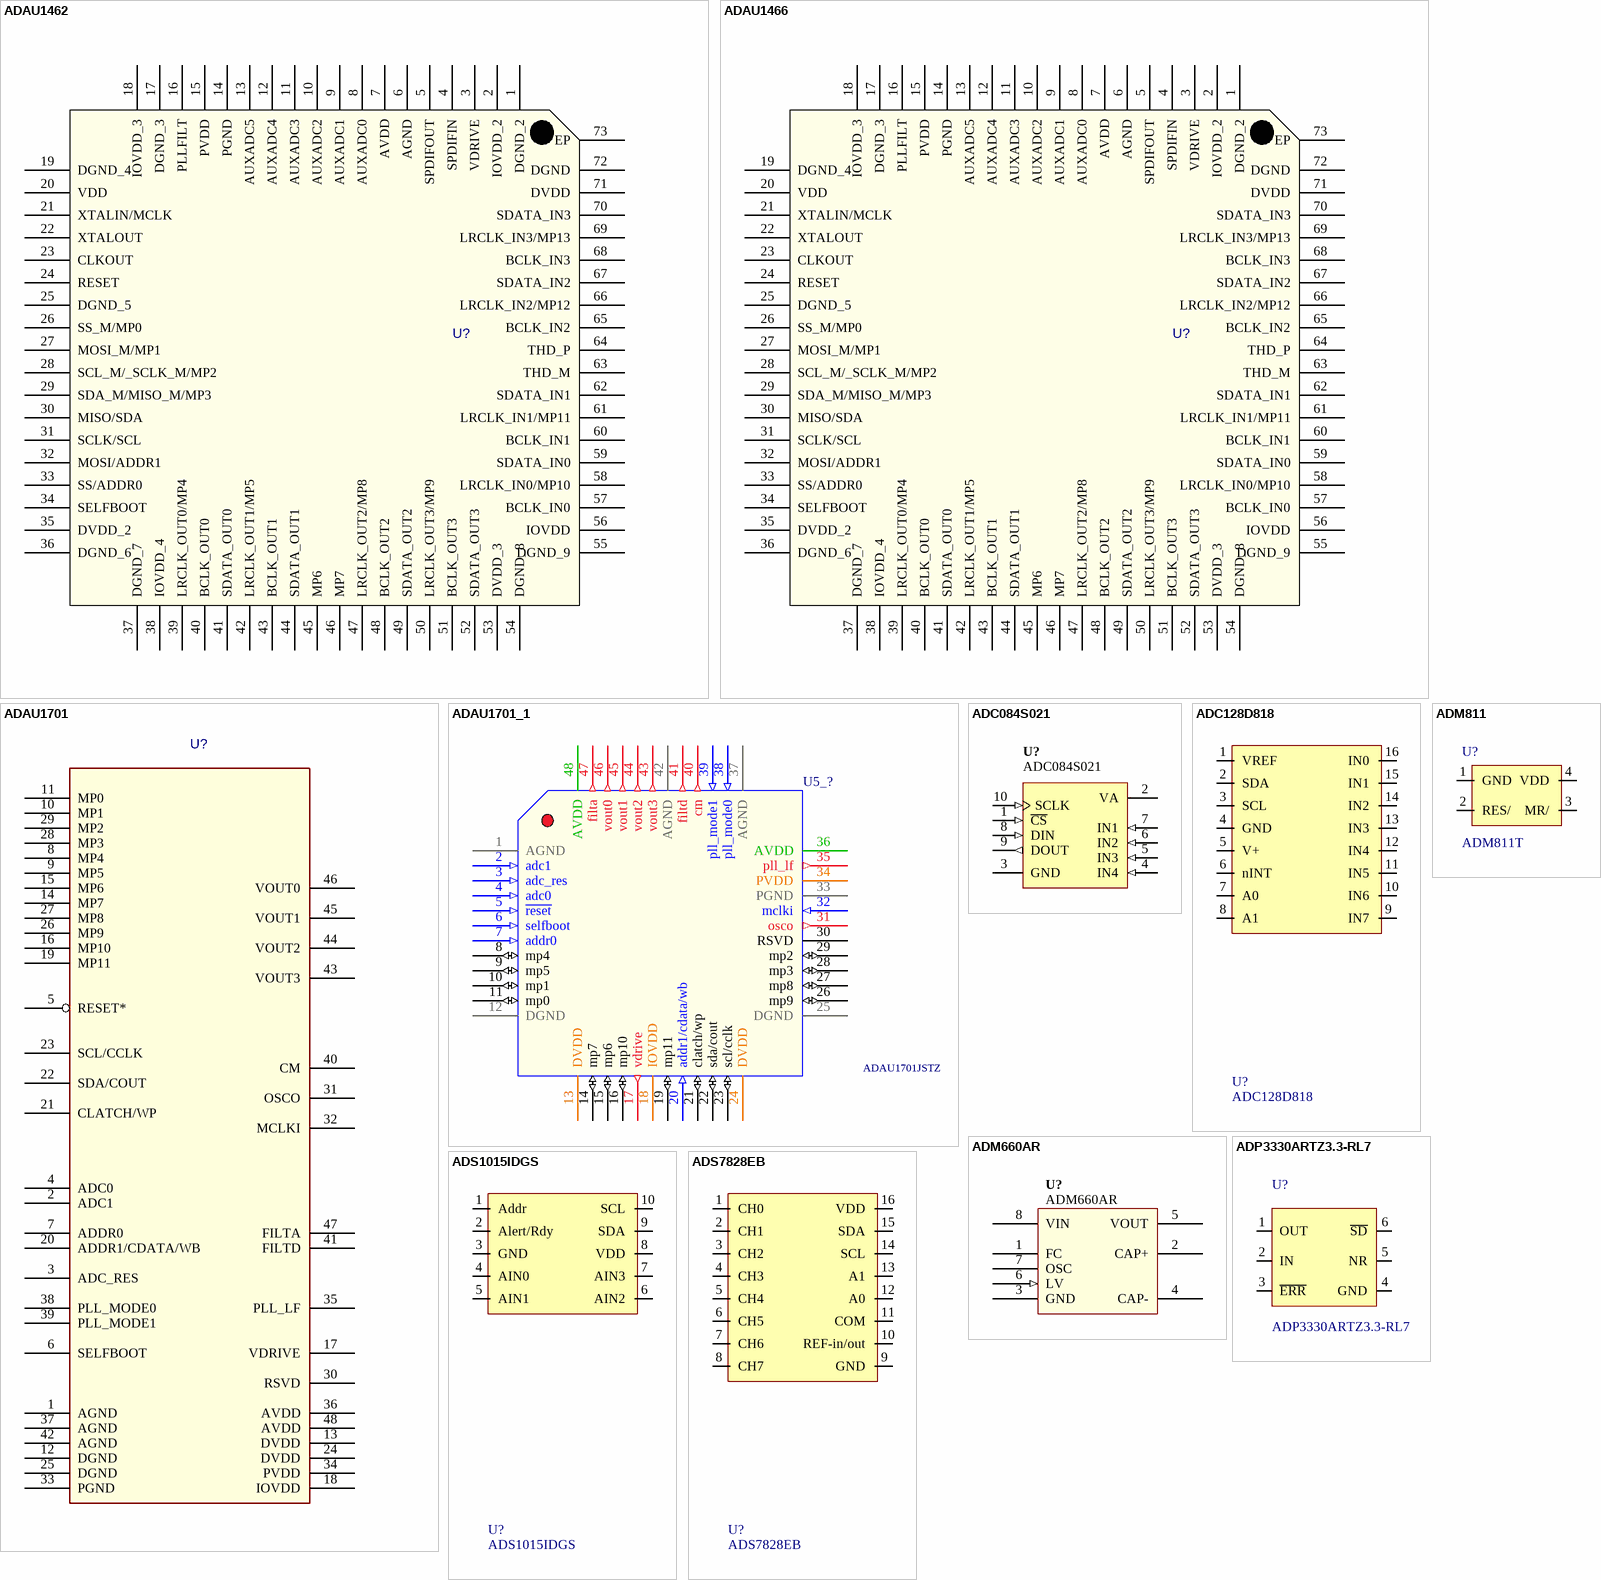
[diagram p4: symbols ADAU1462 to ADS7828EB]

## ADAU1462
designator U?
MPN: ADAU1462WBCPZ300; Hpcode: ICADAU1462 da codificare!; Detail: 7,03€ quota Arrow; Aggiornato: S; Costo: 7,03; ContoLavoro: 0
footprint LFCSP_72_EP (LFCSP 72 Exposed Pad)
footprint LFCSP_72_EP_vias (LFCSP 72 Exposed Pad VIAS)
pins: 1 DGND_2, 2 IOVDD_2, 3 VDRIVE, 4 SPDIFIN, 5 SPDIFOUT, 6 AGND, 7 AVDD, 8 AUXADC0, 9 AUXADC1, 10 AUXADC2, 11 AUXADC3, 12 AUXADC4, 13 AUXADC5, 14 PGND, 15 PVDD, 16 PLLFILT, 17 DGND_3, 18 IOVDD_3, 19 DGND_4, 20 VDD, 21 XTALIN/MCLK, 22 XTALOUT, 23 CLKOUT, 24 RESET, 25 DGND_5, 26 SS_M/MP0, 27 MOSI_M/MP1, 28 SCL_M/_SCLK_M/MP2, 29 SDA_M/MISO_M/MP3, 30 MISO/SDA, 31 SCLK/SCL, 32 MOSI/ADDR1, 33 SS/ADDR0, 34 SELFBOOT, 35 DVDD_2, 36 DGND_6, 37 DGND_7, 38 IOVDD_4, 39 LRCLK_OUT0/MP4, 40 BCLK_OUT0, 41 SDATA_OUT0, 42 LRCLK_OUT1/MP5, 43 BCLK_OUT1, 44 SDATA_OUT1, 45 MP6, 46 MP7, 47 LRCLK_OUT2/MP8, 48 BCLK_OUT2, 49 SDATA_OUT2, 50 LRCLK_OUT3/MP9, 51 BCLK_OUT3, 52 SDATA_OUT3, 53 DVDD_3, 54 DGND_8, 55 DGND_9, 56 IOVDD, 57 BCLK_IN0, 58 LRCLK_IN0/MP10, 59 SDATA_IN0, 60 BCLK_IN1, 61 LRCLK_IN1/MP11, 62 SDATA_IN1, 63 THD_M, 64 THD_P, 65 BCLK_IN2, 66 LRCLK_IN2/MP12, 67 SDATA_IN2, 68 BCLK_IN3, 69 LRCLK_IN3/MP13, 70 SDATA_IN3, 71 DVDD, 72 DGND, 73 EP

## ADAU1466
designator U?
MPN: ADAU1466WBCPZ300; Hpcode: ICADAU1466; Detail: 8,24€ quota Arrow; Aggiornato: S; Costo: 8,24; ContoLavoro: 1
footprint LFCSP_72_EP (LFCSP 72 Exposed Pad)
footprint LFCSP_72_EP_vias (LFCSP 72 Exposed Pad VIAS)
pins: 1 DGND_2, 2 IOVDD_2, 3 VDRIVE, 4 SPDIFIN, 5 SPDIFOUT, 6 AGND, 7 AVDD, 8 AUXADC0, 9 AUXADC1, 10 AUXADC2, 11 AUXADC3, 12 AUXADC4, 13 AUXADC5, 14 PGND, 15 PVDD, 16 PLLFILT, 17 DGND_3, 18 IOVDD_3, 19 DGND_4, 20 VDD, 21 XTALIN/MCLK, 22 XTALOUT, 23 CLKOUT, 24 RESET, 25 DGND_5, 26 SS_M/MP0, 27 MOSI_M/MP1, 28 SCL_M/_SCLK_M/MP2, 29 SDA_M/MISO_M/MP3, 30 MISO/SDA, 31 SCLK/SCL, 32 MOSI/ADDR1, 33 SS/ADDR0, 34 SELFBOOT, 35 DVDD_2, 36 DGND_6, 37 DGND_7, 38 IOVDD_4, 39 LRCLK_OUT0/MP4, 40 BCLK_OUT0, 41 SDATA_OUT0, 42 LRCLK_OUT1/MP5, 43 BCLK_OUT1, 44 SDATA_OUT1, 45 MP6, 46 MP7, 47 LRCLK_OUT2/MP8, 48 BCLK_OUT2, 49 SDATA_OUT2, 50 LRCLK_OUT3/MP9, 51 BCLK_OUT3, 52 SDATA_OUT3, 53 DVDD_3, 54 DGND_8, 55 DGND_9, 56 IOVDD, 57 BCLK_IN0, 58 LRCLK_IN0/MP10, 59 SDATA_IN0, 60 BCLK_IN1, 61 LRCLK_IN1/MP11, 62 SDATA_IN1, 63 THD_M, 64 THD_P, 65 BCLK_IN2, 66 LRCLK_IN2/MP12, 67 SDATA_IN2, 68 BCLK_IN3, 69 LRCLK_IN3/MP13, 70 SDATA_IN3, 71 DVDD, 72 DGND, 73 EP

## ADAU1701
designator U?
MPN: ADAU1701JSTZ; Hpcode: ICADAU1701; Detail: prezzo ns 03/03/2016; Aggiornato: NO; Costo: 4,2030; ContoLavoro: 1
footprint ST_48
pins: 1 AGND, 2 ADC1, 3 ADC_RES, 4 ADC0, 5 RESET*, 6 SELFBOOT, 7 ADDR0, 8 MP4, 9 MP5, 10 MP1, 11 MP0, 12 DGND, 13 DVDD, 14 MP7, 15 MP6, 16 MP10, 17 VDRIVE, 18 IOVDD, 19 MP11, 20 ADDR1/CDATA/WB, 21 CLATCH/WP, 22 SDA/COUT, 23 SCL/CCLK, 24 DVDD, 25 DGND, 26 MP9, 27 MP8, 28 MP3, 29 MP2, 30 RSVD, 31 OSCO, 32 MCLKI, 33 PGND, 34 PVDD, 35 PLL_LF, 36 AVDD, 37 AGND, 38 PLL_MODE0, 39 PLL_MODE1, 40 CM, 41 FILTD, 42 AGND, 43 VOUT3, 44 VOUT2, 45 VOUT1, 46 VOUT0, 47 FILTA, 48 AVDD

## ADAU1701_1
designator U5_?, comment ADAU1701JSTZ
SigmaDSP ADAU1701; HPcode: ICADAU1701; Detail: prezzo ns 03/03/2016; Costo: 4,2030; Aggiornato: NO; ContoLavoro: 0
footprint LQFP-48
pins: 1 AGND (power), 2 adc1 (in), 3 adc_res (in), 4 adc0 (in), 5 ~{reset} (in), 6 selfboot (in), 7 addr0 (in), 8 mp4 (io), 9 mp5 (io), 10 mp1 (io), 11 mp0 (io), 12 DGND (power), 13 DVDD (power), 14 mp7 (io), 15 mp6 (io), 16 mp10 (io), 17 vdrive (out), 18 IOVDD (power), 19 mp11 (io), 20 addr1/cdata/wb (in), 21 clatch/wp (io), 22 sda/cout (io), 23 scl/cclk (io), 24 DVDD (power), 25 DGND (power), 26 mp9 (io), 27 mp8 (io), 28 mp3 (io), 29 mp2 (io), 30 RSVD, 31 osco (out), 32 mclki (in), 33 PGND (power), 34 PVDD (power), 35 pll_lf (out), 36 AVDD (power), 37 AGND (power), 38 pll_mode0 (in), 39 pll_mode1 (in), 40 cm (out), 41 filtd (out), 42 AGND (power), 43 vout3 (out), 44 vout2 (out), 45 vout1 (out), 46 vout0 (out), 47 filta (out), 48 AVDD (power)

## ADC084S021
designator U?
ADC084S021, 8-bit ADC, 4 Channel, 50 ksps to 200ksps, SPI; Bit Width: 8Bits; Max Sample Frequency: 100KHz; Supply Voltage: 2.7 to 5.25V; Aggiornato: NO; Costo: 0
footprint TSSOP50P490-10AN
pins: 1 ~{CS} (in), 2 VA (power), 3 GND (power), 4 IN4 (in), 5 IN3 (in), 6 IN2 (in), 7 IN1 (in), 8 DIN (in), 9 DOUT (out), 10 SCLK (in)

## ADC128D818
designator U?
ADC128D818 12-Bit, 8-Channel, ADC System Monitor With Temperature Sensor, / Internal – External Reference, and I2C Interface; Aggiornato: n; Costo: 2€; ContoLavoro: 0
footprint TSSOP16
pins: 1 VREF, 2 SDA, 3 SCL, 4 GND, 5 V+, 6 nINT, 7 A0, 8 A1, 9 IN7, 10 IN6, 11 IN5, 12 IN4, 13 IN3, 14 IN2, 15 IN1, 16 IN0

## ADM660AR
designator U?
ADM660AR, Switched-Capacitor Voltage Converter/Inverter, 1.5-7V, 100mA, SO8; Max Input Voltage: 7.0 V; Max Output Voltage: -3.0 V; Min Input Voltage: 1.5 V; Min Output Voltage: -14.0 V; Supply Voltage: mV; Aggiornato: NO; Costo: 0
footprint SOIC127P600-8
pins: 1 FC, 2 CAP+, 3 GND, 4 CAP-, 5 VOUT, 6 LV (in), 7 OSC, 8 VIN

## ADM811
designator U?, comment ADM811T
Detail: (prezzo GaGi); Costo: 0,132; Aggiornato: SI; ContoLavoro: 0
footprint SOT143M
pins: 1 GND, 2 RES/, 3 MR/, 4 VDD

## ADP3330ARTZ3.3-RL7
designator U?
Costo: 0; Aggiornato: NO; ContoLavoro: 1,228
footprint SOT23-6N (SOT23, 3-Leads, Body 2.9x1.3mm, Pitch 0.95mm, Lead Span 2.5mm, IPC Medium Density)
pins: 1 OUT, 2 IN, 3 ~{ERR}, 4 GND, 5 NR, 6 ~{SD}

## ADS1015IDGS
designator U?
12-Bit 3.3kSPS 4-Ch Delta-Sigma ADC With PGA, Oscillator, VREF, Comparator, and I2C; Detail: 1,25€ quota Avnet; Aggiornato: n; Costo: 1,25; ContoLavoro: 0
footprint VSSOP10 (Footprint not found)
pins: 1 Addr, 2 Alert/Rdy, 3 GND, 4 AIN0, 5 AIN1, 6 AIN2, 7 AIN3, 8 VDD, 9 SDA, 10 SCL

## ADS7828EB
designator U?
12-Bit 50kSPS 8-Ch Delta-Sigma ADC, VREF, I2C interface; Detail: 1,25€ quota Avnet; Aggiornato: s; Costo: 1,25; ContoLavoro: 0
footprint TSSOP16
pins: 1 CH0, 2 CH1, 3 CH2, 4 CH3, 5 CH4, 6 CH5, 7 CH6, 8 CH7, 9 GND, 10 REF-in/out, 11 COM, 12 A0, 13 A1, 14 SCL, 15 SDA, 16 VDD

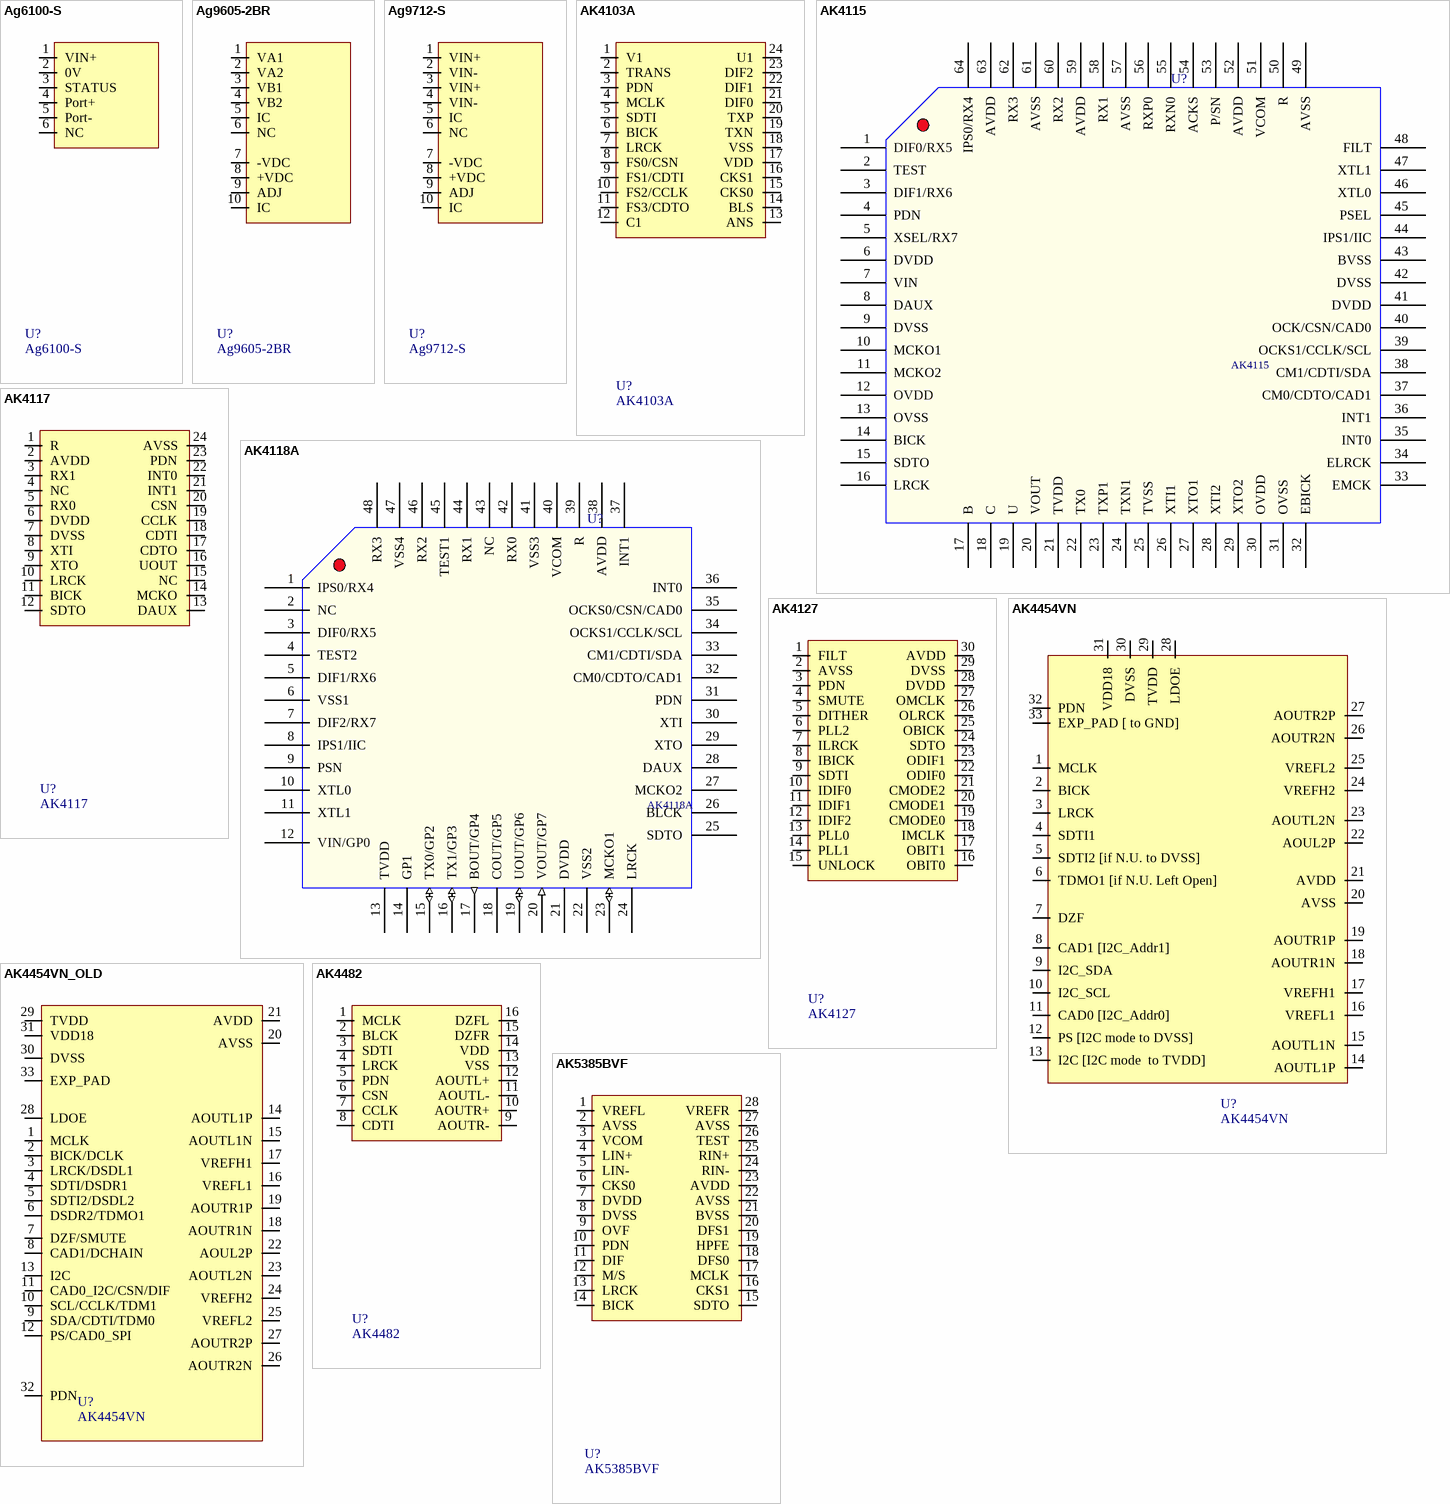
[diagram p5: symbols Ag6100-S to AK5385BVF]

## Ag6100-S
designator U?
Ag6100-S POE PSE 39W; Aggiornato: s; Costo: 7; ContoLavoro: 0
footprint SILVERTEL-POE-PSE-SIL
pins: 1 VIN+, 2 0V, 3 STATUS, 4 Port+, 5 Port-, 6 NC

## Ag9605-2BR
designator U?
Ag9605-2BR POE 5V; Aggiornato: NO; Costo: 0
pins: 1 VA1, 2 VA2, 3 VB1, 4 VB2, 5 IC, 6 NC, 7 -VDC, 8 +VDC, 9 ADJ, 10 IC

## Ag9712-S
designator U?
Ag9712-S POE PD 12V 12W; Aggiornato: s; Costo: 5,6; ContoLavoro: 0
footprint SILVERTEL-POE-PD-SIL
pins: 1 VIN+, 2 VIN-, 3 VIN+, 4 VIN-, 5 IC, 6 NC, 7 -VDC, 8 +VDC, 9 ADJ, 10 IC

## AK4103A
designator U?
AK4103A AES3 DIT TX; HPcode: ICAK4103A; Aggiornato: s; Costo: 1,20; ContoLavoro: 1
footprint VSOP24
pins: 1 V1, 2 TRANS, 3 PDN, 4 MCLK, 5 SDTI, 6 BICK, 7 LRCK, 8 FS0/CSN, 9 FS1/CDTI, 10 FS2/CCLK, 11 FS3/CDTO, 12 C1, 13 ANS, 14 BLS, 15 CKS0, 16 CKS1, 17 VDD, 18 VSS, 19 TXN, 20 TXP, 21 DIF0, 22 DIF1, 23 DIF2, 24 U1

## AK4115
designator U?
AKM AK4115; Costo: 2,30; Aggiornato: SI; ContoLavoro: 0
footprint LQFP-64 (Footprint not found)
pins: 1 DIF0/RX5, 2 TEST, 3 DIF1/RX6, 4 PDN, 5 XSEL/RX7, 6 DVDD, 7 VIN, 8 DAUX, 9 DVSS, 10 MCKO1, 11 MCKO2, 12 OVDD, 13 OVSS, 14 BICK, 15 SDTO, 16 LRCK, 17 B, 18 C, 19 U, 20 VOUT, 21 TVDD, 22 TX0, 23 TXP1, 24 TXN1, 25 TVSS, 26 XTI1, 27 XTO1, 28 XTI2, 29 XTO2, 30 OVDD, 31 OVSS, 32 EBICK, 33 EMCK, 34 ELRCK, 35 INT0, 36 INT1, 37 CM0/CDTO/CAD1, 38 CM1/CDTI/SDA, 39 OCKS1/CCLK/SCL, 40 OCK/CSN/CAD0, 41 DVDD, 42 DVSS, 43 BVSS, 44 IPS1/IIC, 45 PSEL, 46 XTL0, 47 XTL1, 48 FILT, 49 AVSS, 50 R, 51 VCOM, 52 AVDD, 53 P/SN, 54 ACKS, 55 RXN0, 56 RXP0, 57 AVSS, 58 RX1, 59 AVDD, 60 RX2, 61 AVSS, 62 RX3, 63 AVDD, 64 IPS0/RX4

## AK4117
designator U?
AK4117 DIT; Aggiornato: n; Costo: 0
footprint VSOP24
pins: 1 R, 2 AVDD, 3 RX1, 4 NC, 5 RX0, 6 DVDD, 7 DVSS, 8 XTI, 9 XTO, 10 LRCK, 11 BICK, 12 SDTO, 13 DAUX, 14 MCKO, 15 NC, 16 UOUT, 17 CDTO, 18 CDTI, 19 CCLK, 20 CSN, 21 INT1, 22 INT0, 23 PDN, 24 AVSS

## AK4118A
designator U?
AKM AK4118A; HPcode: ICAK4118A; Costo: 1,21; Aggiornato: SI; ContoLavoro: 1
footprint LQFP-48
pins: 1 IPS0/RX4, 2 NC, 3 DIF0/RX5, 4 TEST2, 5 DIF1/RX6, 6 VSS1, 7 DIF2/RX7, 8 IPS1/IIC, 9 PSN, 10 XTL0, 11 XTL1, 12 VIN/GP0, 13 TVDD, 14 GP1, 15 TX0/GP2 (io), 16 TX1/GP3 (io), 17 BOUT/GP4 (out), 18 COUT/GP5, 19 UOUT/GP6 (io), 20 VOUT/GP7 (in), 21 DVDD, 22 VSS2, 23 MCKO1 (io), 24 LRCK, 25 SDTO, 26 BLCK, 27 MCKO2, 28 DAUX, 29 XTO, 30 XTI, 31 PDN, 32 CM0/CDTO/CAD1, 33 CM1/CDTI/SDA, 34 OCKS1/CCLK/SCL, 35 OCKS0/CSN/CAD0, 36 INT0, 37 INT1, 38 AVDD, 39 R, 40 VCOM, 41 VSS3, 42 RX0, 43 NC, 44 RX1, 45 TEST1, 46 RX2, 47 VSS4, 48 RX3

## AK4127
designator U?
AK4127 SRC; Aggiornato: n; Costo: 0,92; ContoLavoro: 0
footprint VSOP30 (Footprint not found)
pins: 1 FILT, 2 AVSS, 3 PDN, 4 SMUTE, 5 DITHER, 6 PLL2, 7 ILRCK, 8 IBICK, 9 SDTI, 10 IDIF0, 11 IDIF1, 12 IDIF2, 13 PLL0, 14 PLL1, 15 UNLOCK, 16 OBIT0, 17 OBIT1, 18 IMCLK, 19 CMODE0, 20 CMODE1, 21 CMODE2, 22 ODIF0, 23 ODIF1, 24 SDTO, 25 OBICK, 26 OLRCK, 27 OMCLK, 28 DVDD, 29 DVSS, 30 AVDD

## AK4454VN
designator U?
4-Channel Differential 32-bit S/D ADC Label semplificati per I2C e TDM/I2S; Detail: Costo stimato x 100 pz; HPcode: ICAK4454VN; Aggiornato: S; Costo: 2,5; ContoLavoro: 1
footprint QFN32
pins: 1 MCLK, 2 BICK, 3 LRCK, 4 SDTI1, 5 SDTI2 [if N.U. to DVSS], 6 TDMO1 [if N.U. Left Open], 7 DZF, 8 CAD1 [I2C_Addr1], 9 I2C_SDA, 10 I2C_SCL, 11 CAD0 [I2C_Addr0], 12 PS [I2C mode to DVSS], 13 I2C [I2C mode  to TVDD], 14 AOUTL1P, 15 AOUTL1N, 16 VREFL1, 17 VREFH1, 18 AOUTR1N, 19 AOUTR1P, 20 AVSS, 21 AVDD, 22 AOUL2P, 23 AOUTL2N, 24 VREFH2, 25 VREFL2, 26 AOUTR2N, 27 AOUTR2P, 28 LDOE, 29 TVDD, 30 DVSS, 31 VDD18, 32 PDN, 33 EXP_PAD [ to GND]

## AK4454VN_OLD
designator U?, comment AK4454VN
4-Channel Differential 32-bit S/D ADC; Detail: Costo stimato x 100 pz; Aggiornato: SI; Costo: 2,5; ContoLavoro: 0
footprint QFN32
pins: 1 MCLK, 2 BICK/DCLK, 3 LRCK/DSDL1, 4 SDTI/DSDR1, 5 SDTI2/DSDL2, 6 DSDR2/TDMO1, 7 DZF/SMUTE, 8 CAD1/DCHAIN, 9 SDA/CDTI/TDM0, 10 SCL/CCLK/TDM1, 11 CAD0_I2C/CSN/DIF, 12 PS/CAD0_SPI, 13 I2C, 14 AOUTL1P, 15 AOUTL1N, 16 VREFL1, 17 VREFH1, 18 AOUTR1N, 19 AOUTR1P, 20 AVSS, 21 AVDD, 22 AOUL2P, 23 AOUTL2N, 24 VREFH2, 25 VREFL2, 26 AOUTR2N, 27 AOUTR2P, 28 LDOE, 29 TVDD, 30 DVSS, 31 VDD18, 32 PDN, 33 EXP_PAD

## AK4482
designator U?
AK4482 DAC; HPcode: ICAK4482; Aggiornato: SI; Costo: 0,46; ContoLavoro: 1
footprint TSSOP16
pins: 1 MCLK, 2 BLCK, 3 SDTI, 4 LRCK, 5 PDN, 6 CSN, 7 CCLK, 8 CDTI, 9 AOUTR-, 10 AOUTR+, 11 AOUTL-, 12 AOUTL+, 13 VSS, 14 VDD, 15 DZFR, 16 DZFL

## AK5385BVF
designator U?
AK5385BVF 24Bit 192kHz adc SIGMADELTA; HPcode: ICAK5385BVF; Aggiornato: S; Costo: 1,9351; ContoLavoro: 1
footprint VSOP28
pins: 1 VREFL, 2 AVSS, 3 VCOM, 4 LIN+, 5 LIN-, 6 CKS0, 7 DVDD, 8 DVSS, 9 OVF, 10 PDN, 11 DIF, 12 M/S, 13 LRCK, 14 BICK, 15 SDTO, 16 CKS1, 17 MCLK, 18 DFS0, 19 HPFE, 20 DFS1, 21 BVSS, 22 AVSS, 23 AVDD, 24 RIN-, 25 RIN+, 26 TEST, 27 AVSS, 28 VREFR

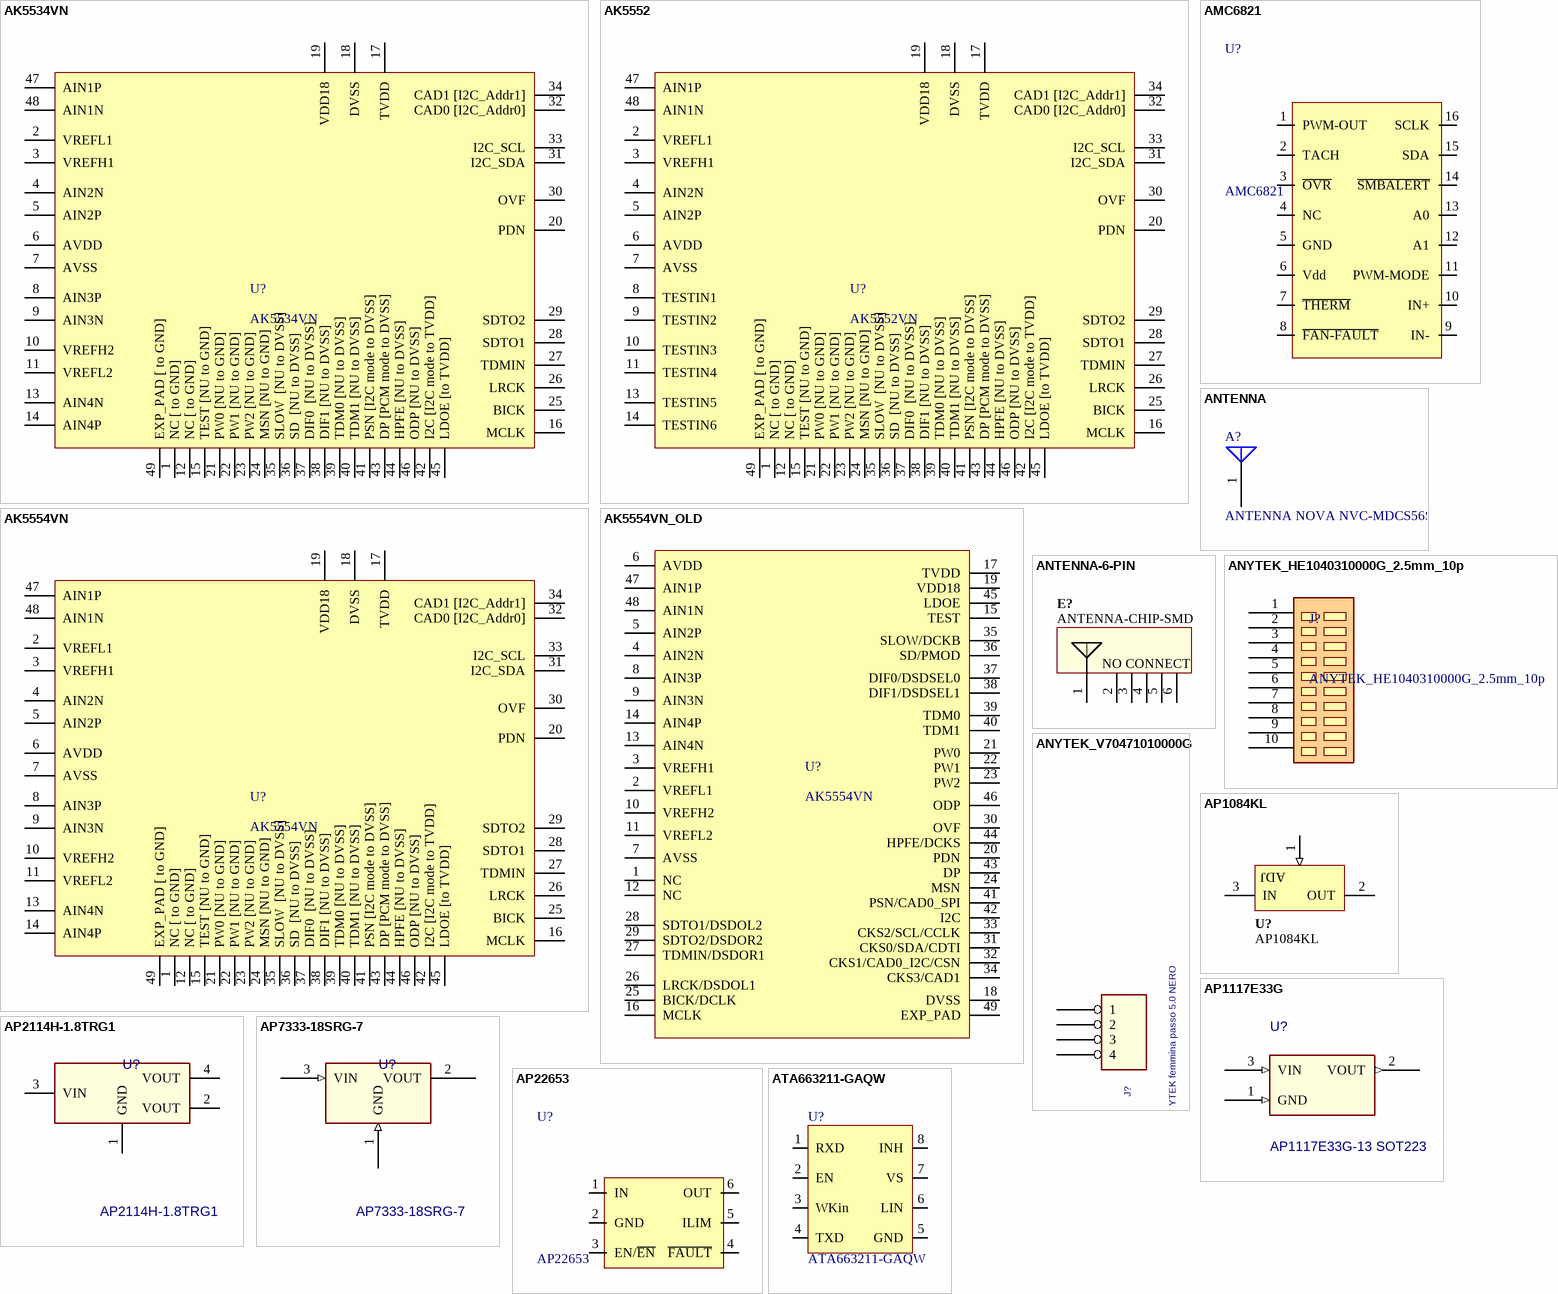
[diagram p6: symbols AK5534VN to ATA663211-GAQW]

## AK5534VN
designator U?
4-Channel Differential 32-bit S/D ADC Label semplificati per I2C e TDM/I2S; MPN: AK553AVN; Aggiornato: s; HPcode: ICAK5534VN - da codificare; Costo: 3,0; ContoLavoro: 1
footprint QFN48 (48 pin QFN package 7x7 mm)
pins: 1 NC [ to GND] "No internal bonding. Connect to AVSS.", 2 VREFL1 "ADC Low Level Voltage Reference Input Pin", 3 VREFH1 "ADC High Level Voltage Reference Input Pin", 4 AIN2N, 5 AIN2P, 6 AVDD "Analog Power Supply Pin (AIN1-4), 4.5-5.5 V", 7 AVSS "Analog Ground Pin (AIN1-4)", 8 AIN3P, 9 AIN3N, 10 VREFH2, 11 VREFL2, 12 NC [ to GND] "No internal bonding. Connect to AVSS", 13 AIN4N, 14 AIN4P, 15 TEST [NU to GND] "TEST Enable Pin", 16 MCLK "Master Clock Input Pin", 17 TVDD "Digital I/O Buffers and LDO Power Supply Pin, 1.7-1.98 V (LDOE pin= “L”) or 3.0-3.6 V (LDOE pin= “H”).", 18 DVSS "Digital Ground Pin", 19 VDD18, 20 PDN "Reset & Power Down Pin", 21 PW0 [NU to GND] "Power Management Pin, Channel Summation Select Pin1", 22 PW1 [NU to GND] "Power Management Pin, Channel Summation Select Pin2", 23 PW2 [NU to GND] "Power Management Pin, Channel Summation Select Pin 3", 24 MSN [NU to GND] "Master/Slave Select Pin", 25 BICK "Audio Serial Data Clock Input/Output Pin in PCM & Slave/Master Mode (This pin is pull down by 100 kΩ internally.)", 26 LRCK "Channel Clock Input/Output Pin in PCM & Slave/Master Mode", 27 TDMIN "TDMIN/DSDOR1", 28 SDTO1 "SDTO1/DSDOL2", 29 SDTO2 "SDTO2/DSDOR2", 30 OVF, 31 I2C_SDA "CKS0/SDA/CDTI", 32 CAD0 [I2C_Addr0] "CKS1/CAD0_I2C/CSN", 33 I2C_SCL "CKS2/SCL/CCLK", 34 CAD1 [I2C_Addr1] "CKS3/CAD1", 35 SLOW  [NU to DVSS] "SLOW/DCKB", 36 SD  [NU to DVSS] "SD/PMOD", 37 DIF0  [NU to DVSS] "DIF0/DSDSEL0", 38 DIF1 [NU to DVSS] "DIF1/DSDSEL1", 39 TDM0 [NU to DVSS] "TDM0", 40 TDM1 [NU to DVSS] "TDM1", 41 PSN [I2C mode to DVSS] "PSN/CAD0_SPI", 42 I2C [I2C mode to TVDD] "I2C", 43 DP [PCM mode to DVSS] "DP", 44 HPFE [NU to DVSS] "HPFE/DCKS", 45 LDOE [to TVDD] "LDOE", 46 ODP [NU to DVSS] "ODP", 47 AIN1P, 48 AIN1N, 49 EXP_PAD [ to GND] "EXP_PAD"

## AK5552
designator U?, comment AK5552VN
2-Channel Differential 32-bit S/D ADC Label semplificati per I2C e TDM/I2S; MPN: AK5552AVN; Aggiornato: s; HPcode: ICAK5552VN da generare; Costo: 2,5; ContoLavoro: 1
footprint QFN48 (48 pin QFN package 7x7 mm)
pins: 1 NC [ to GND] "No internal bonding. Connect to AVSS.", 2 VREFL1 "ADC Low Level Voltage Reference Input Pin", 3 VREFH1 "ADC High Level Voltage Reference Input Pin", 4 AIN2N, 5 AIN2P, 6 AVDD "Analog Power Supply Pin (AIN1-4), 4.5-5.5 V", 7 AVSS "Analog Ground Pin (AIN1-4)", 8 TESTIN1 "AIN3P", 9 TESTIN2 "AIN3N", 10 TESTIN3 "VREFH2", 11 TESTIN4 "VREFL2", 12 NC [ to GND] "No internal bonding. Connect to AVSS", 13 TESTIN5 "AIN4N", 14 TESTIN6 "AIN4P", 15 TEST [NU to GND] "TEST Enable Pin", 16 MCLK "Master Clock Input Pin", 17 TVDD "Digital I/O Buffers and LDO Power Supply Pin, 1.7-1.98 V (LDOE pin= “L”) or 3.0-3.6 V (LDOE pin= “H”).", 18 DVSS "Digital Ground Pin", 19 VDD18, 20 PDN "Reset & Power Down Pin", 21 PW0 [NU to GND] "Power Management Pin, Channel Summation Select Pin1", 22 PW1 [NU to GND] "Power Management Pin, Channel Summation Select Pin2", 23 PW2 [NU to GND] "Power Management Pin, Channel Summation Select Pin 3", 24 MSN [NU to GND] "Master/Slave Select Pin", 25 BICK "Audio Serial Data Clock Input/Output Pin in PCM & Slave/Master Mode (This pin is pull down by 100 kΩ internally.)", 26 LRCK "Channel Clock Input/Output Pin in PCM & Slave/Master Mode", 27 TDMIN "TDMIN/DSDOR1", 28 SDTO1 "SDTO1/DSDOL2", 29 SDTO2 "SDTO2/DSDOR2", 30 OVF, 31 I2C_SDA "CKS0/SDA/CDTI", 32 CAD0 [I2C_Addr0] "CKS1/CAD0_I2C/CSN", 33 I2C_SCL "CKS2/SCL/CCLK", 34 CAD1 [I2C_Addr1] "CKS3/CAD1", 35 SLOW  [NU to DVSS] "SLOW/DCKB", 36 SD  [NU to DVSS] "SD/PMOD", 37 DIF0  [NU to DVSS] "DIF0/DSDSEL0", 38 DIF1 [NU to DVSS] "DIF1/DSDSEL1", 39 TDM0 [NU to DVSS] "TDM0", 40 TDM1 [NU to DVSS] "TDM1", 41 PSN [I2C mode to DVSS] "PSN/CAD0_SPI", 42 I2C [I2C mode to TVDD] "I2C", 43 DP [PCM mode to DVSS] "DP", 44 HPFE [NU to DVSS] "HPFE/DCKS", 45 LDOE [to TVDD] "LDOE", 46 ODP [NU to DVSS] "ODP", 47 AIN1P, 48 AIN1N, 49 EXP_PAD [ to GND] "EXP_PAD"

## AK5554VN
designator U?
4-Channel Differential 32-bit S/D ADC Label semplificati per I2C e TDM/I2S; MPN: AK555AVN; Aggiornato: s; HPcode: ICAK5554VN; Costo: 4,0; ContoLavoro: 1
footprint QFN48 (48 pin QFN package 7x7 mm)
pins: 1 NC [ to GND] "No internal bonding. Connect to AVSS.", 2 VREFL1 "ADC Low Level Voltage Reference Input Pin", 3 VREFH1 "ADC High Level Voltage Reference Input Pin", 4 AIN2N, 5 AIN2P, 6 AVDD "Analog Power Supply Pin (AIN1-4), 4.5-5.5 V", 7 AVSS "Analog Ground Pin (AIN1-4)", 8 AIN3P, 9 AIN3N, 10 VREFH2, 11 VREFL2, 12 NC [ to GND] "No internal bonding. Connect to AVSS", 13 AIN4N, 14 AIN4P, 15 TEST [NU to GND] "TEST Enable Pin", 16 MCLK "Master Clock Input Pin", 17 TVDD "Digital I/O Buffers and LDO Power Supply Pin, 1.7-1.98 V (LDOE pin= “L”) or 3.0-3.6 V (LDOE pin= “H”).", 18 DVSS "Digital Ground Pin", 19 VDD18, 20 PDN "Reset & Power Down Pin", 21 PW0 [NU to GND] "Power Management Pin, Channel Summation Select Pin1", 22 PW1 [NU to GND] "Power Management Pin, Channel Summation Select Pin2", 23 PW2 [NU to GND] "Power Management Pin, Channel Summation Select Pin 3", 24 MSN [NU to GND] "Master/Slave Select Pin", 25 BICK "Audio Serial Data Clock Input/Output Pin in PCM & Slave/Master Mode (This pin is pull down by 100 kΩ internally.)", 26 LRCK "Channel Clock Input/Output Pin in PCM & Slave/Master Mode", 27 TDMIN "TDMIN/DSDOR1", 28 SDTO1 "SDTO1/DSDOL2", 29 SDTO2 "SDTO2/DSDOR2", 30 OVF, 31 I2C_SDA "CKS0/SDA/CDTI", 32 CAD0 [I2C_Addr0] "CKS1/CAD0_I2C/CSN", 33 I2C_SCL "CKS2/SCL/CCLK", 34 CAD1 [I2C_Addr1] "CKS3/CAD1", 35 SLOW  [NU to DVSS] "SLOW/DCKB", 36 SD  [NU to DVSS] "SD/PMOD", 37 DIF0  [NU to DVSS] "DIF0/DSDSEL0", 38 DIF1 [NU to DVSS] "DIF1/DSDSEL1", 39 TDM0 [NU to DVSS] "TDM0", 40 TDM1 [NU to DVSS] "TDM1", 41 PSN [I2C mode to DVSS] "PSN/CAD0_SPI", 42 I2C [I2C mode to TVDD] "I2C", 43 DP [PCM mode to DVSS] "DP", 44 HPFE [NU to DVSS] "HPFE/DCKS", 45 LDOE [to TVDD] "LDOE", 46 ODP [NU to DVSS] "ODP", 47 AIN1P, 48 AIN1N, 49 EXP_PAD [ to GND] "EXP_PAD"

## AK5554VN_OLD
designator U?, comment AK5554VN
4-Channel Differential 32-bit S/D ADC; Aggiornato: s; Costo: 4,0; ContoLavoro: 0
footprint QFN48 (48 pin QFN package 7x7 mm)
pins: 1 NC "No internal bonding. Connect to AVSS.", 2 VREFL1 "ADC Low Level Voltage Reference Input Pin", 3 VREFH1 "ADC High Level Voltage Reference Input Pin", 4 AIN2N, 5 AIN2P, 6 AVDD "Analog Power Supply Pin (AIN1-4), 4.5-5.5 V", 7 AVSS "Analog Ground Pin (AIN1-4)", 8 AIN3P, 9 AIN3N, 10 VREFH2, 11 VREFL2, 12 NC "No internal bonding. Connect to AVSS", 13 AIN4N, 14 AIN4P, 15 TEST "TEST Enable Pin", 16 MCLK "Master Clock Input Pin", 17 TVDD "Digital I/O Buffers and LDO Power Supply Pin, 1.7-1.98 V (LDOE pin= “L”) or 3.0-3.6 V (LDOE pin= “H”).", 18 DVSS "Digital Ground Pin", 19 VDD18, 20 PDN "Reset & Power Down Pin", 21 PW0 "Power Management Pin, Channel Summation Select Pin1", 22 PW1 "Power Management Pin, Channel Summation Select Pin2", 23 PW2 "Power Management Pin, Channel Summation Select Pin 3", 24 MSN "Master/Slave Select Pin", 25 BICK/DCLK "Audio Serial Data Clock Input/Output Pin in PCM & Slave/Master Mode (This pin is pull down by 100 kΩ internally.)", 26 LRCK/DSDOL1 "Channel Clock Input/Output Pin in PCM & Slave/Master Mode", 27 TDMIN/DSDOR1, 28 SDTO1/DSDOL2, 29 SDTO2/DSDOR2, 30 OVF, 31 CKS0/SDA/CDTI, 32 CKS1/CAD0_I2C/CSN, 33 CKS2/SCL/CCLK, 34 CKS3/CAD1, 35 SLOW/DCKB, 36 SD/PMOD, 37 DIF0/DSDSEL0, 38 DIF1/DSDSEL1, 39 TDM0, 40 TDM1, 41 PSN/CAD0_SPI, 42 I2C, 43 DP, 44 HPFE/DCKS, 45 LDOE, 46 ODP, 47 AIN1P, 48 AIN1N, 49 EXP_PAD

## AMC6821
designator U?
AMC6821 I2C GPIO EXPANDER; Detail: RS 2,28 € pz>75 , TI 1€ pz>1000; Costo: 1; Aggiornato: s; ContoLavoro: 0
footprint SSOP_16_QSOP16_TI
pins: 1 PWM-OUT, 2 TACH, 3 ~{OVR}, 4 NC, 5 GND, 6 Vdd, 7 ~{THERM}, 8 ~{FAN-FAULT}, 9 IN-, 10 IN+, 11 PWM-MODE, 12 A1, 13 A0, 14 ~{SMBALERT}, 15 SDA, 16 SCLK

## ANTENNA
designator A?, comment ANTENNA NOVA NVC-MDCS56S  (no BOM)
Aggiornato: NO; Costo: 0
footprint ANTENNA NOVA NVC-MDCS56S
pins: 1

## ANTENNA-6-PIN
designator E?, comment ANTENNA-CHIP-SMD
Antenna, 2.45GHz Chip SMD 5.5 X 7.35MM; Impedence: 50 Ohms; Aggiornato: NO; Costo: 0
footprint ANTENNA-2-45GHZ-6PIN
pins: 1, 2, 3, 4, 5, 6

## ANYTEK_HE1040310000G_2.5mm_10p
designator J?
ContoLavoro: 1; Costo: 0
footprint ANYTEK_HE1040310000G (Footprint not found)
pins: 1, 2, 3, 4, 5, 6, 7, 8, 9, 10

## ANYTEK_V70471010000G
designator J?, comment 4 PINS ANYTEK femmina passo 5.0 NERO
HEADER_4 ANYTEK FEMALE Passo 5.0 V70471010000G BLACK / Compatibili: / ANYTEK FEMALE Passo 5.0 V70471510000G GREEN / ANYTEK FEMALE Passo 5.08 V70451010000G BLACK / ANYTEK FEMALE Passo 5.08 V70451510000GGREEN / PHOENIX IC 2.5/ 4-G-5,08 BK (1731086) / PHOENIX IC 2.5/ 4-G-5,08 (1786420) / PHOENIX IC 2.5 HC/ 4-G-5,08 (1943328) / PHOENIX IC 2.5 HC/ 4-G-5,08 BK (1704087); Costo: 0; Aggiornato: NO
footprint PHOENIX_ANYTEK_V704710100000G
pins: 1, 2, 3, 4

## AP1084KL
designator U?
AP1084KL, 5A Low Dropout Positive Adjustable Regulator; Max Input Voltage: 12V; Max Output Current: 5.1A; Max Output Voltage: mV; Min Input Voltage: -0.3V; Aggiornato: NO; Costo: 0
footprint TO254P-3N
pins: 1 ADJ (in), 2 OUT (power), 3 IN (power)

## AP1117E33G
designator U?, comment AP1117E33G-13 SOT223
Costo: 0,185; DeviceFunction: Voltage Regulator; Aggiornato: NO; ContoLavoro: 0
footprint SOT223
pins: 1 GND (in), 2 VOUT (out), 3 VIN (in)

## AP2114H-1.8TRG1
designator U?
LDO AP7333-18SRG-7 300mA 1,8V SOT-23; Detail: 0,051€ RS Pz>50; Costo: 0,051; DeviceFunction: Voltage Regulator; Aggiornato: N; ContoLavoro: 0
footprint SOT223
pins: 1 GND, 2 VOUT, 3 VIN, 4 VOUT

## AP7333-18SRG-7
designator U?
LDO AP7333-18SRG-7 300mA 1,8V SOT-23; Detail: 0,067€ RS Pz>50; Costo: 0,067; DeviceFunction: Voltage Regulator; Aggiornato: N; ContoLavoro: 0
footprint SOT-23_UP
pins: 1 GND (in), 2 VOUT, 3 VIN (in)

## AP22653
designator U?
Costo: 0,20; Aggiornato: NO; ContoLavoro: 0
footprint SOT26 (Footprint not found)
pins: 1 IN, 2 GND, 3 EN/~{EN}, 4 ~{FAULT}, 5 ILIM, 6 OUT

## ATA663211-GAQW
designator U?
HPcode: ICATA663211-GAQW; Detail: € Mouser Pz>100; Costo: 0,7; Aggiornato: NO; ContoLavoro: 1
footprint SO8
pins: 1 RXD, 2 EN, 3 WKin, 4 TXD, 5 GND, 6 LIN, 7 VS, 8 INH

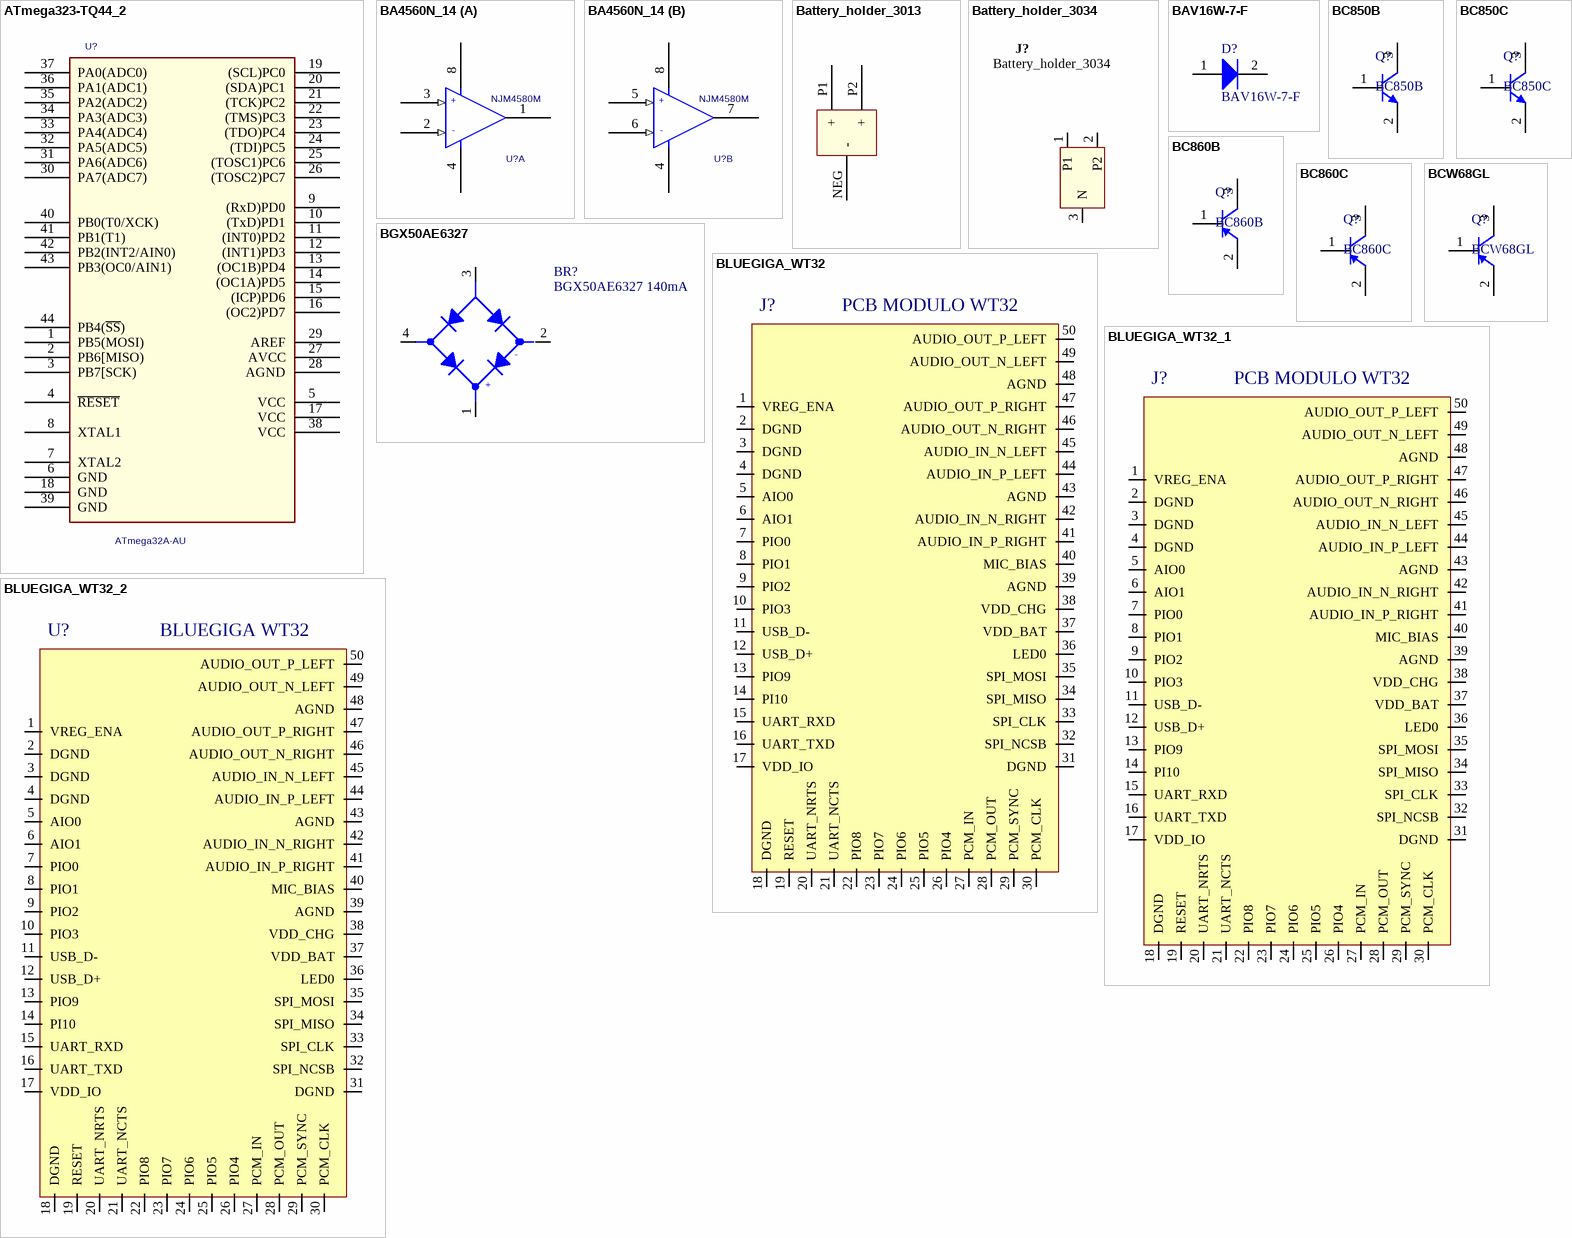
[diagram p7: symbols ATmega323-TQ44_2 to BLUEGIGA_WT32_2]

## ATmega323-TQ44_2
designator U?, comment ATmega32A-AU
Aggiornato: NO; Costo: 0
footprint TQFP44
footprint TQFP-44
pins: 1 PB5(MOSI), 2 PB6[MISO), 3 PB7[SCK), 4 ~{RESET}, 5 VCC, 6 GND, 7 XTAL2, 8 XTAL1, 9 (RxD)PD0, 10 (TxD)PD1, 11 (INT0)PD2, 12 (INT1)PD3, 13 (OC1B)PD4, 14 (OC1A)PD5, 15 (ICP)PD6, 16 (OC2)PD7, 17 VCC, 18 GND, 19 (SCL)PC0, 20 (SDA)PC1, 21 (TCK)PC2, 22 (TMS)PC3, 23 (TDO)PC4, 24 (TDI)PC5, 25 (TOSC1)PC6, 26 (TOSC2)PC7, 27 AVCC, 28 AGND, 29 AREF, 30 PA7(ADC7), 31 PA6(ADC6), 32 PA5(ADC5), 33 PA4(ADC4), 34 PA3(ADC3), 35 PA2(ADC2), 36 PA1(ADC1), 37 PA0(ADC0), 38 VCC, 39 GND, 40 PB0(T0/XCK), 41 PB1(T1), 42 PB2(INT2/AIN0), 43 PB3(OC0/AIN1), 44 PB4(~{SS})

## BA4560N_14
designator U?, comment NJM4580M
Hpcode: ICNJM4580M; Aggiornato: NO; Costo: 0
footprint SIP/TM/L.800/8
footprint SO8
part A pins: 1 OUT, 2 -IN (in), 3 +IN (in), 4 GND SIGNAL (power), 8 +V1 (power)
part B pins: 4 GND SIGNAL (power), 5 +IN (in), 6 -IN (in), 7 OUT, 8 +V1 (power)

## Battery_holder_3013
designator J?, comment Battery holder 3013
Battery holder  CR1612/1616/1620/1632 (3013, Keystone); Detail: 0,49€ RS pz>60; Costo: 0,49; Aggiornato: NO; ContoLavoro: 0
footprint Battery_holder_16mm_thd
pins: NEG -, P1 +, P2 +
2 alternate drawings of the same symbol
